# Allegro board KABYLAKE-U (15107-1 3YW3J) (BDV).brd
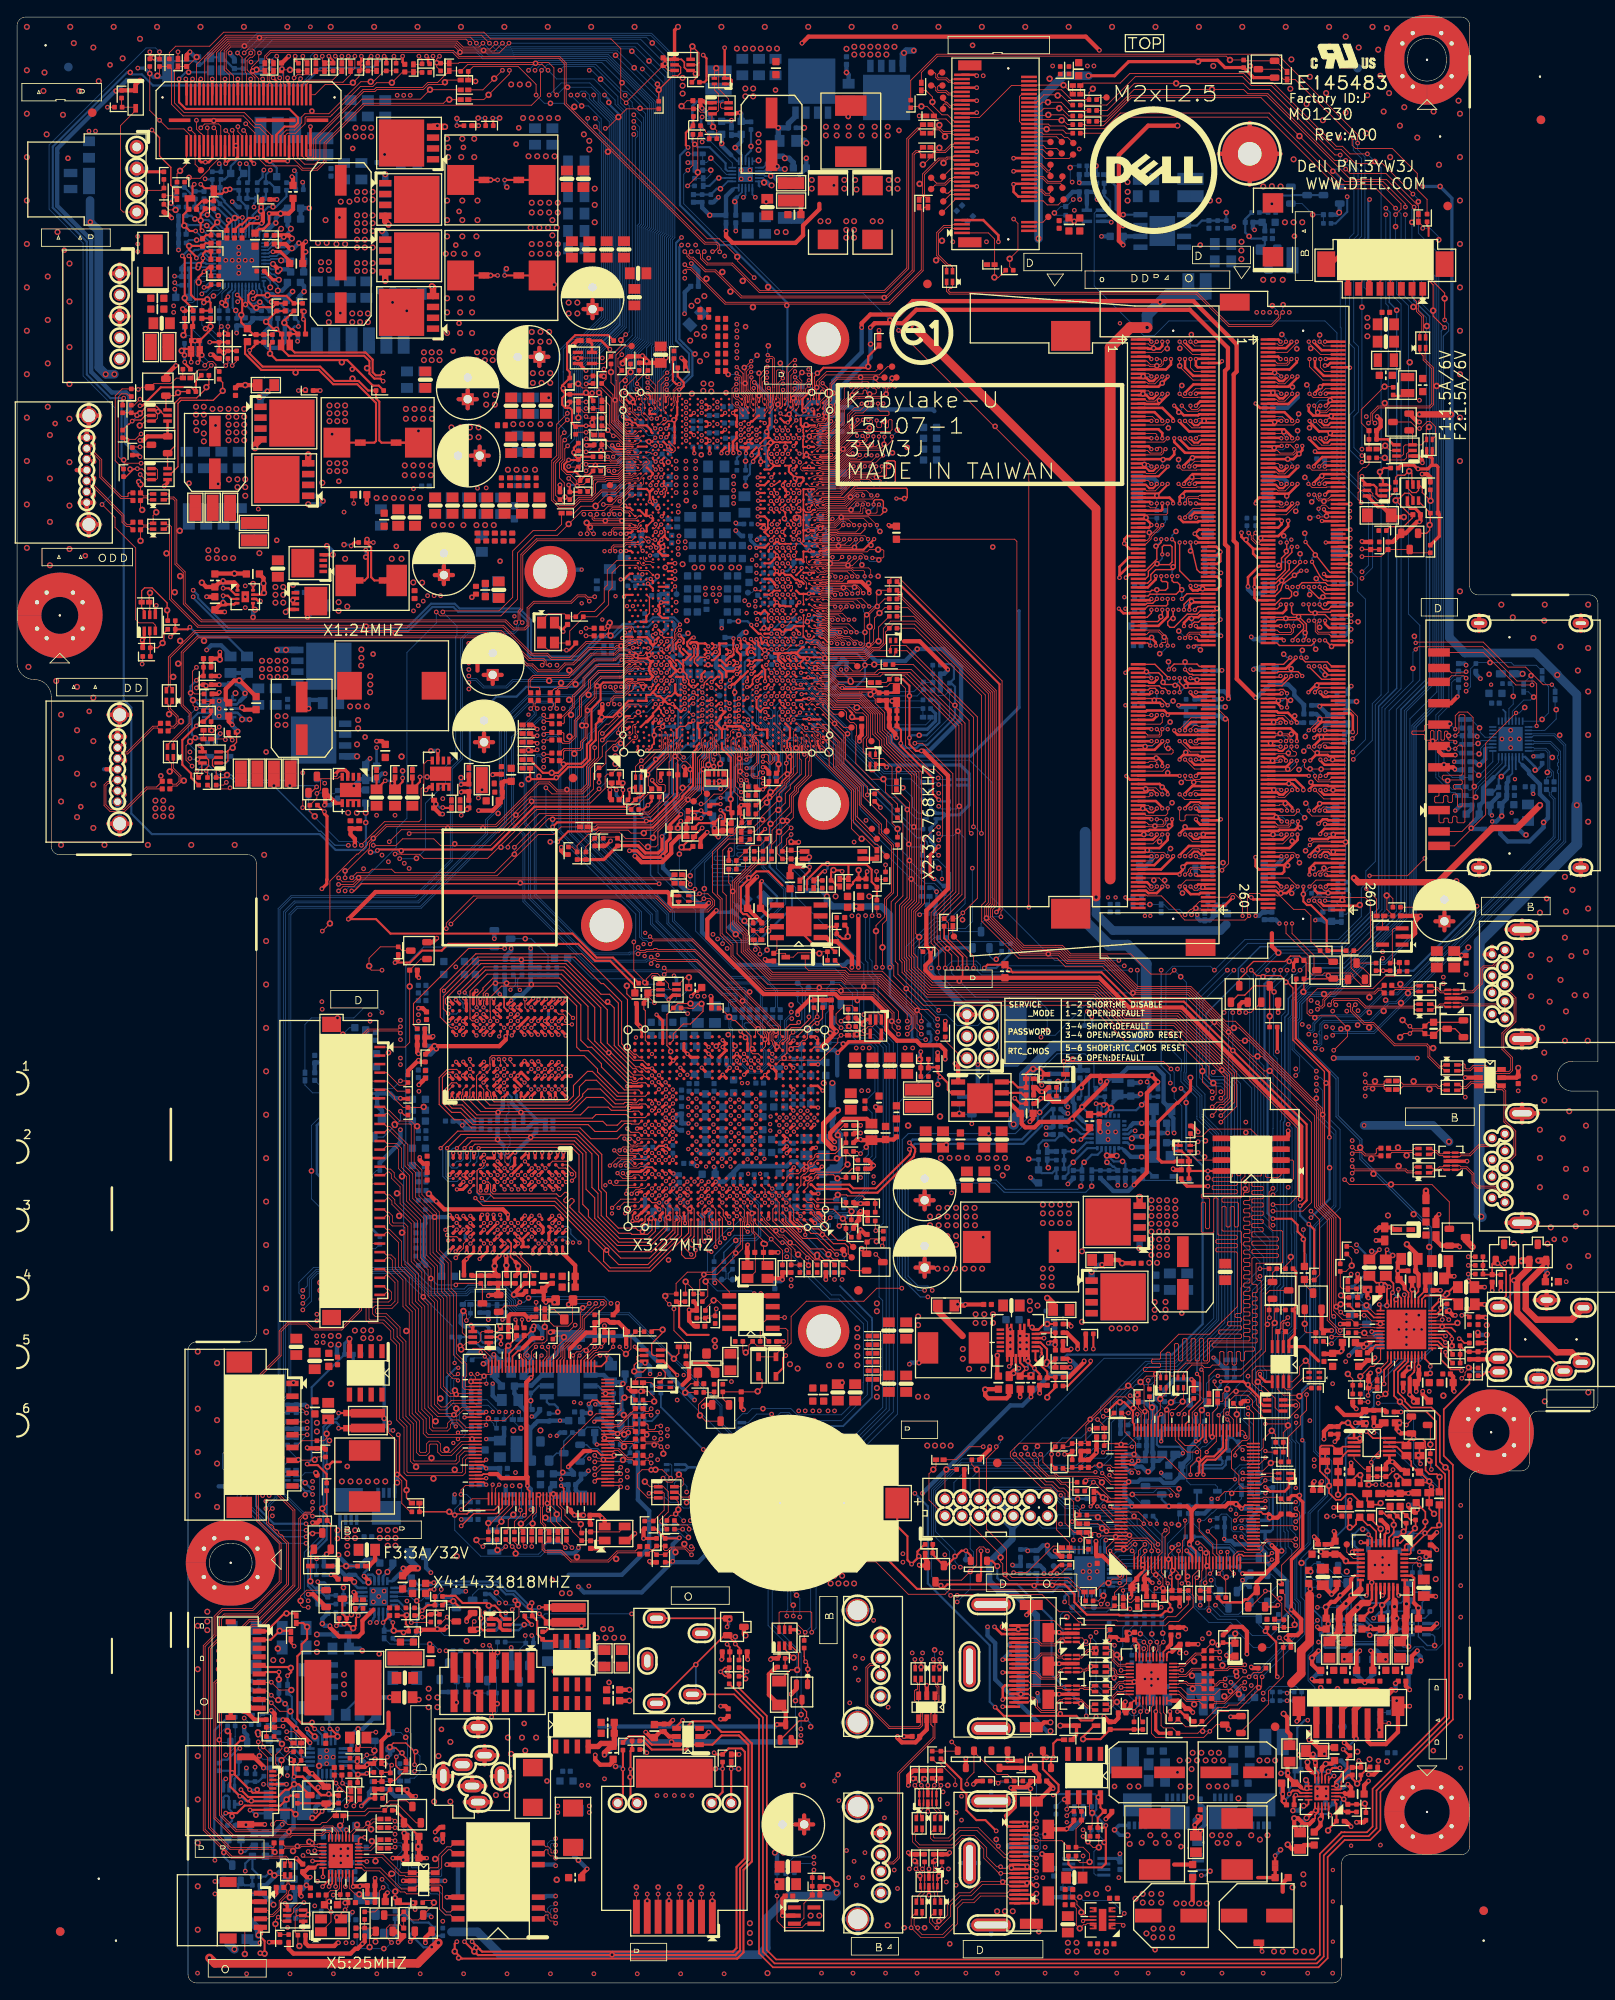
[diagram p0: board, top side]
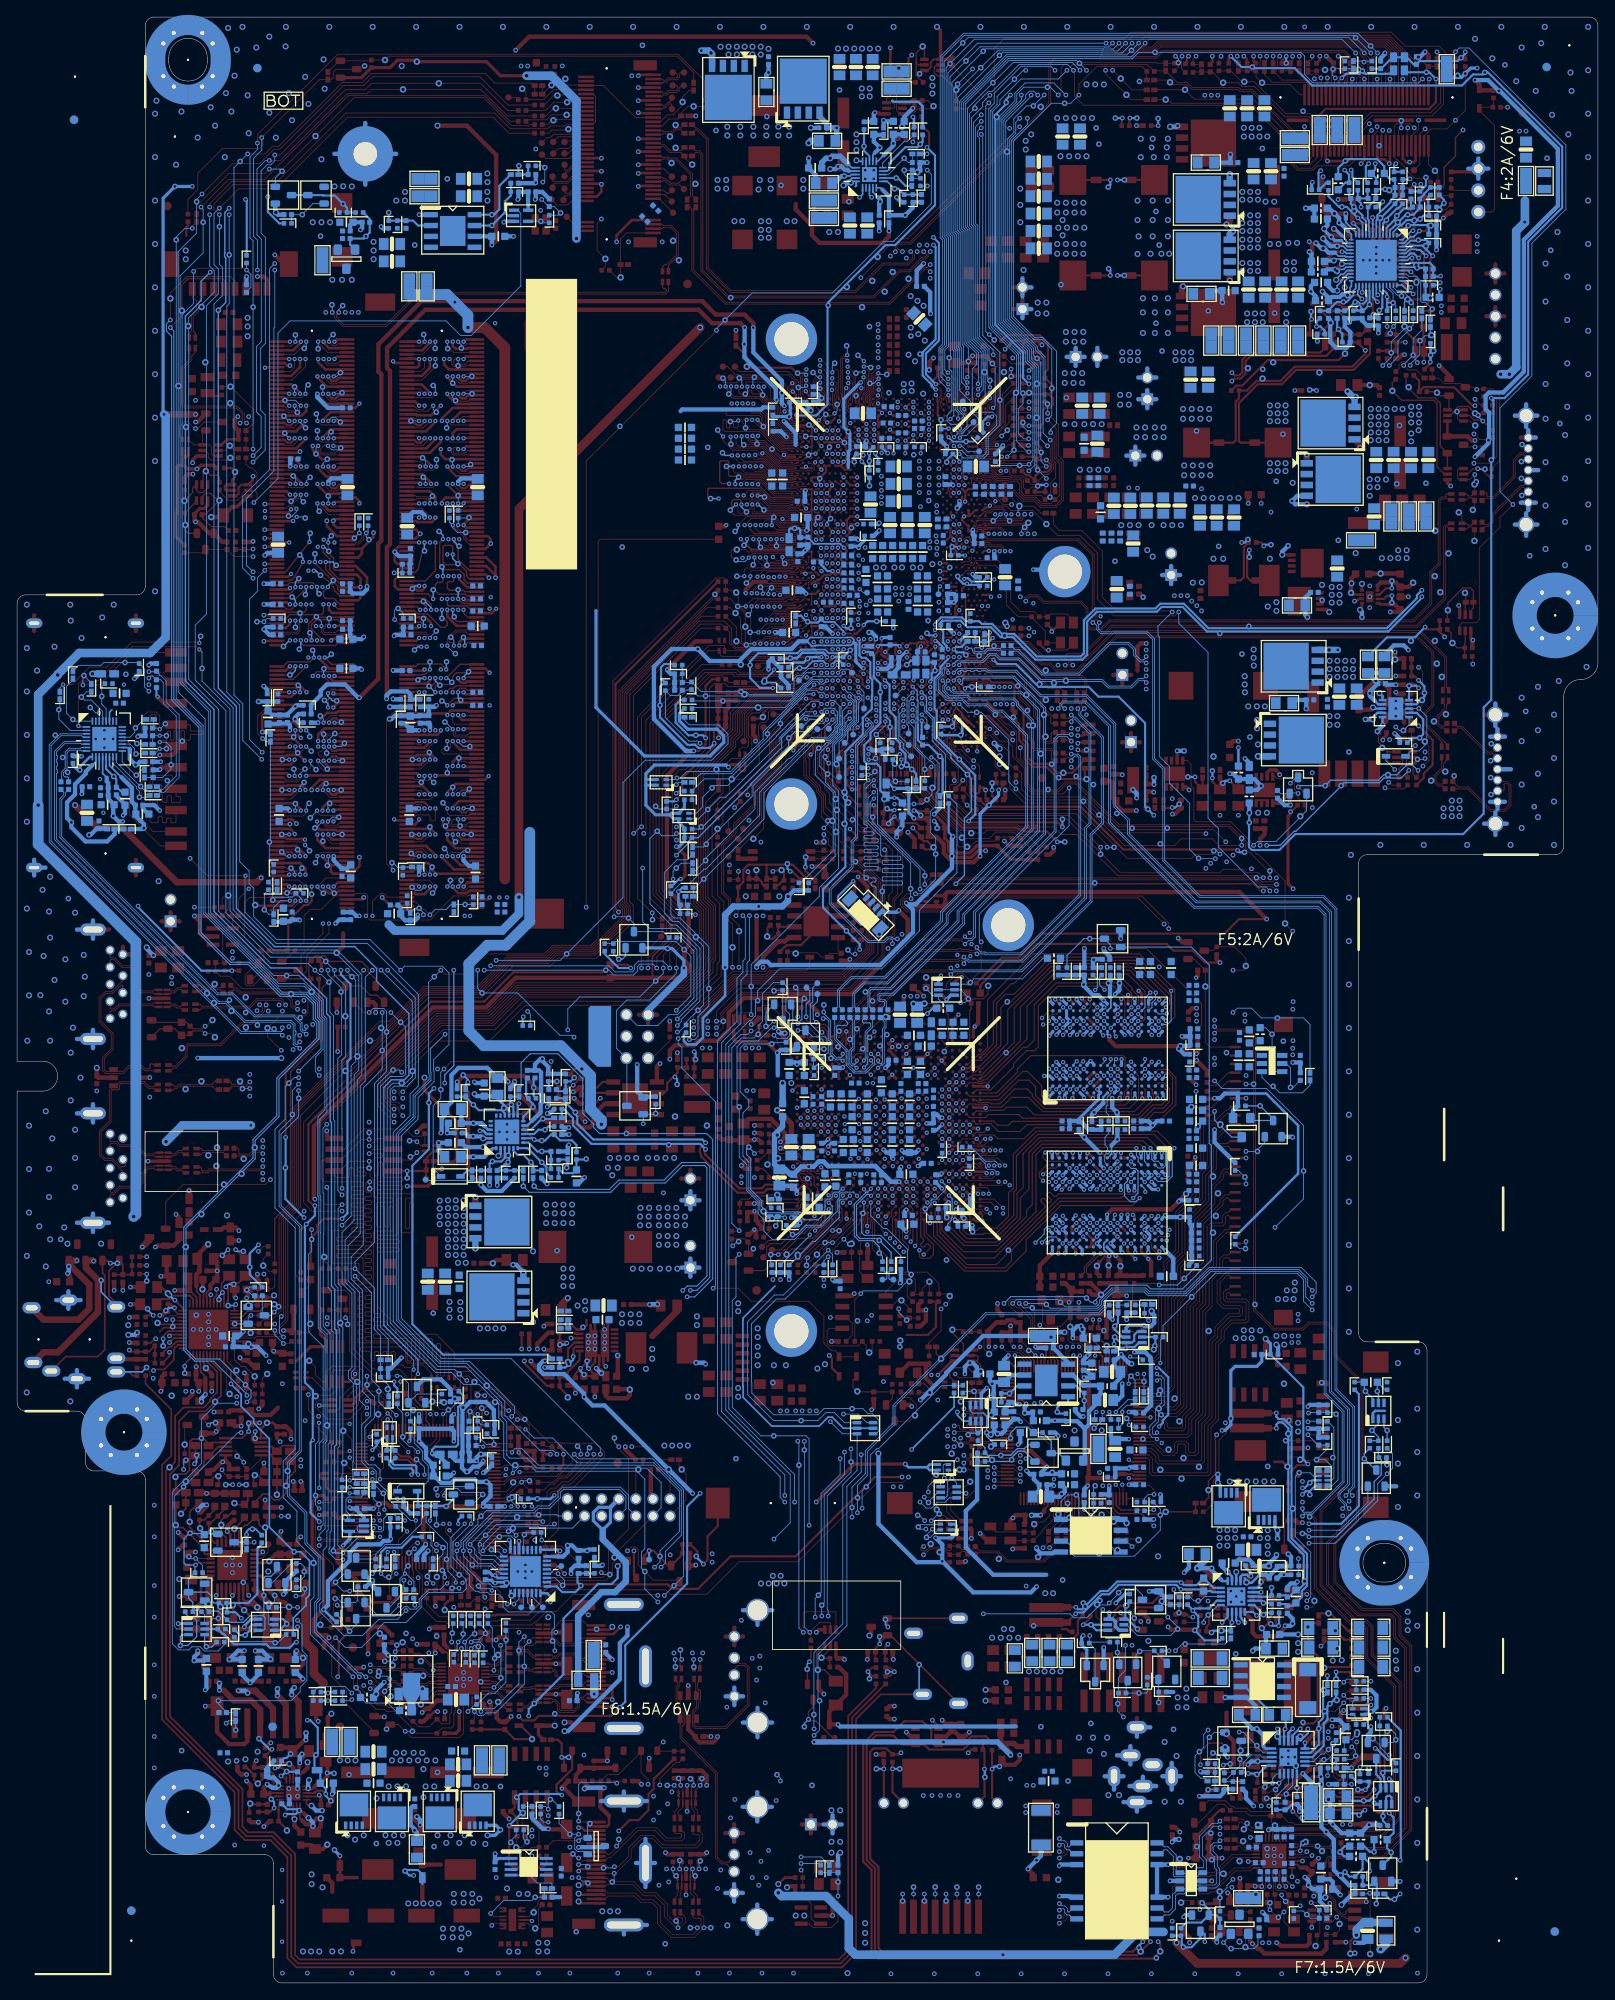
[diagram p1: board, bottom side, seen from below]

Outline 185 x 230 mm; copper layers: TOP, L2GND, L3, L4, L5GND, BOTTOM. Coordinates in mm from the lower left corner of the outline.
Outline path: 0,229 0,154.5 arc(0.59,153.09) 2,152.5 arc(3.41,151.91) 4,150.5 4,133 arc(4.29,132.29) 5,132 27,132 arc(27.71,131.71) 28,131 28,76 arc(27.71,75.29) 27,75 21,75 arc(20.29,74.71) 20,74 20,1 arc(20.29,0.29) 21,0 154,0 arc(154.71,0.29) 155,1 155,14 arc(155.29,14.71) 156,15 169,15 arc(169.71,15.29) 170,16 170,58.9 arc(170.29,59.61) 171,59.9 176,59.9 arc(176.71,60.19) 177,60.9 177,65.9 arc(177.29,66.61) 178,66.9 184,66.9 arc(184.71,67.19) 185,67.9 185,104.34 182,104.34 arc(180.25,106.09) 182,107.84 185,107.84 185,161.4 arc(184.71,162.11) 184,162.4 171,162.4 arc(170.29,162.69) 170,163.4 170,229 arc(169.71,229.71) 169,230 1,230 arc(0.29,229.71) 0,229 ; 24.75,51.4 25.25,51.4 arc(27.5,49.15) 25.25,46.9 24.75,46.9 arc(22.5,49.15) 24.75,51.4 ; 162.75,225.25 arc(165,227.5) 167.25,225.25 167.25,224.75 arc(165,222.5) 162.75,224.75 162.75,225.25

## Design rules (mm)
constraint set DEFAULT: min track width 0.127, pair gap 0.102
net group AUD_LINK_BCLK: nets AUD_LINK_BCLK HDA_BITCLK_CPU
net group CLK_WLAN_N: nets CLK_WLAN_N NGFF_REFCLKN0
net group CLK_WLAN_P: nets CLK_WLAN_P NGFF_REFCLKP0
net group DP_LANE0N_C: nets DP_LANE0N_C EDP_TX_CPU_N0
net group DP_LANE0P_C: nets DP_LANE0P_C EDP_TX_CPU_P0
net group DP_LANE1N_C: nets DP_LANE1N_C EDP_TX_CPU_N1
net group DP_LANE1P_C: nets DP_LANE1P_C EDP_TX_CPU_P1
net group GND: nets EC_AGND GND_AUD
net group GPU_ODT-MW: nets FBA_CMD2 FBA_CMD18
net group HDMI1_CK+: nets HDMI1_CK+ HDMI1_CK+_C
net group HDMI1_CK-: nets HDMI1_CK- HDMI1_CK-_C
net group HDMI1_D0+: nets HDMI1_D0+ HDMI1_D0+_C
net group HDMI1_D0-: nets HDMI1_D0- HDMI1_D0-_C
net group HDMI1_D1+: nets HDMI1_D1+ HDMI1_D1+_C
net group HDMI1_D1-: nets HDMI1_D1- HDMI1_D1-_C
net group HDMI1_D2+: nets HDMI1_D2+ HDMI1_D2+_C
net group HDMI1_D2-: nets HDMI1_D2- HDMI1_D2-_C
net group HDMI1_DATA_CPU_N0: nets HDMI1_DATA_CPU_N0 HDMI1_DATA_IC_N0
net group HDMI1_DATA_CPU_N1: nets HDMI1_DATA_CPU_N1 HDMI1_DATA_IC_N1
net group HDMI1_DATA_CPU_N2: nets HDMI1_DATA_CPU_N2 HDMI1_DATA_IC_N2
net group HDMI1_DATA_CPU_N3: nets HDMI1_DATA_CPU_N3 HDMI1_DATA_IC_N3
net group HDMI1_DATA_CPU_P0: nets HDMI1_DATA_CPU_P0 HDMI1_DATA_IC_P0
net group HDMI1_DATA_CPU_P1: nets HDMI1_DATA_CPU_P1 HDMI1_DATA_IC_P1
net group HDMI1_DATA_CPU_P2: nets HDMI1_DATA_CPU_P2 HDMI1_DATA_IC_P2
net group HDMI1_DATA_CPU_P3: nets HDMI1_DATA_CPU_P3 HDMI1_DATA_IC_P3
net group HDMI_LANE0_DN: nets HDMI_LANE0_DN HDMI_LANE0_IC_DN
net group HDMI_LANE0_DP: nets HDMI_LANE0_DP HDMI_LANE0_IC_DP
net group HDMI_LANE1_DN: nets HDMI_LANE1_DN HDMI_LANE1_IC_DN
net group HDMI_LANE1_DP: nets HDMI_LANE1_DP HDMI_LANE1_IC_DP
net group HDMI_LANE2_DN: nets HDMI_LANE2_DN HDMI_LANE2_IC_DN
net group HDMI_LANE2_DP: nets HDMI_LANE2_DP HDMI_LANE2_IC_DP
net group HDMI_LANE3_DN: nets HDMI_LANE3_DN HDMI_LANE3_IC_DN
net group HDMI_LANE3_DP: nets HDMI_LANE3_DP HDMI_LANE3_IC_DP
net group HSI_C_DN8: nets HSI_C_DN8 PCIE_RX_CPU_N8
net group HSI_C_DP8: nets HSI_C_DP8 PCIE_RX_CPU_P8
net group HSI_LAN_DN1_R: nets HSI_LAN_DN1_R PCIE_RX_CPU_N4
net group HSI_LAN_DP1_R: nets HSI_LAN_DP1_R PCIE_RX_CPU_P4
net group LAN_MDI2_DN: nets LAN_MDI2_DN LAN_MDI2_DN_R
net group LAN_MDI2_DP: nets LAN_MDI2_DP LAN_MDI2_DP_R
net group LAN_MDI3_DN: nets LAN_MDI3_DN LAN_MDI3_DN_R
net group LAN_MDI3_DP: nets LAN_MDI3_DP LAN_MDI3_DP_R
net group M1_SMB_CLK: nets M1_SMB_CLK SMB_CLK_RESUME
net group M1_SMB_DATA: nets M1_SMB_DATA SMB_DATA_RESUME
net group M_A_CLK0: nets M_A_CLK0 M_A_CLK#0
net group M_A_DQS0: nets M_A_DQS_DN0 M_A_DQS_DP0
net group M_A_DQS1: nets M_A_DQS_DN1 M_A_DQS_DP1
net group M_A_DQS2: nets M_A_DQS_DN2 M_A_DQS_DP2
net group M_A_DQS3: nets M_A_DQS_DN3 M_A_DQS_DP3
net group M_A_DQS4: nets M_A_DQS_DN4 M_A_DQS_DP4
net group M_A_DQS5: nets M_A_DQS_DN5 M_A_DQS_DP5
net group M_A_DQS6: nets M_A_DQS_DN6 M_A_DQS_DP6
net group M_A_DQS7: nets M_A_DQS_DN7 M_A_DQS_DP7
net group M_B_CLK0: nets M_B_CLK0 M_B_CLK#0
net group M_B_DQS0: nets M_B_DQS_DN0 M_B_DQS_DP0
net group M_B_DQS1: nets M_B_DQS_DN1 M_B_DQS_DP1
net group M_B_DQS2: nets M_B_DQS_DN2 M_B_DQS_DP2
net group M_B_DQS3: nets M_B_DQS_DN3 M_B_DQS_DP3
net group M_B_DQS4: nets M_B_DQS_DN4 M_B_DQS_DP4
net group M_B_DQS5: nets M_B_DQS_DN5 M_B_DQS_DP5
net group M_B_DQS6: nets M_B_DQS_DN6 M_B_DQS_DP6
net group M_B_DQS7: nets M_B_DQS_DN7 M_B_DQS_DP7
net group NGFF_PCIE0_RXN: nets NGFF_PCIE0_RXN PCIE_RX_CPU_N5
net group NGFF_PCIE0_RXP: nets NGFF_PCIE0_RXP PCIE_RX_CPU_P5
net group PCIE_TX_CON_N4: nets PCIE_TX_CON_N4 PCIE_TX_CPU_N4
net group PCIE_TX_CON_N8: nets PCIE_TX_CON_N8 PCIE_TX_CPU_N8
net group PCIE_TX_CON_P4: nets PCIE_TX_CON_P4 PCIE_TX_CPU_P4
net group PCIE_TX_CON_P8: nets PCIE_TX_CON_P8 PCIE_TX_CPU_P8
net group PEG_C_TXN0: nets PEG_C_TXN0 PEG_TXN0
net group PEG_C_TXN1: nets PEG_C_TXN1 PEG_TXN1
net group PEG_C_TXN2: nets PEG_C_TXN2 PEG_TXN2
net group PEG_C_TXN3: nets PEG_C_TXN3 PEG_TXN3
net group PEG_C_TXP0: nets PEG_C_TXP0 PEG_TXP0
net group PEG_C_TXP1: nets PEG_C_TXP1 PEG_TXP1
net group PEG_C_TXP2: nets PEG_C_TXP2 PEG_TXP2
net group PEG_C_TXP3: nets PEG_C_TXP3 PEG_TXP3
net group PEG_CLK_CPU: nets PEG_CLK_CPU PEG_CLK_XDP
net group PEG_CLK_CPU#: nets PEG_CLK_CPU# PEG_CLK_XDP#
net group POWER_CPU_PLL_20_5: nets 1V_VCCPRIM 1V_VCCSRAM
net group RCOMP_PCIE: nets PEG_RCOMPN_CPU PEG_RCOMPP_CPU
net group SD_CLK_C_1: nets SD_CLK_C_1 SP3
net group SD_CMD: nets SD_CMD SP4
net group SD_DAT0: nets SD_DAT0 SP2
net group SD_DAT1: nets SD_DAT1 SP1
net group SD_DAT2: nets SD_DAT2 SP6
net group SD_DAT3: nets SD_DAT3 SP5
net group SIDE_USB3_RX0+: nets SIDE_USB3_RX0+ USB30_RX_CPU_P0
net group SIDE_USB3_RX0-: nets SIDE_USB3_RX0- USB30_RX_CPU_N0
net group SIDE_USB3_RX1+: nets SIDE_USB3_RX1+ USB30_RX_CPU_P1
net group SIDE_USB3_RX1-: nets SIDE_USB3_RX1- USB30_RX_CPU_N1
net group SMB_CLK_MAIN: nets SMB_CLK_MAIN XDP_SMBCLK
net group SMB_DATA_MAIN: nets SMB_DATA_MAIN XDP_SMBDAT
net group SPI_CLK: nets SPI_CLK SPI_CLK_CPU
net group SPI_CS0_N: nets SPI_CS0_N SPI_CS_CPU_N0
net group SPI_MOSI: nets SPI_MOSI SPI_SI_CPU
net group STRAP: nets GPP_B18/GSPI0_MOSI GPP_B22/GSPI1_MOSI
net group TRANSFORNER_20_10: nets MCT_R_1 XRF_TDC2
net group USB2_N0: nets USB2_N0 USBP0N_EXT
net group USB2_N3: nets USB2_N3 USB3N_EXT
net group USB2_N4: nets USB2_N4 USB_PCH_DN4_NN
net group USB2_N5: nets USB2_N5 USB_TOUCH_N
net group USB2_N6: nets USB2_N6 USB2_NGFF_N6
net group USB2_NGFF_P6: nets USB2_NGFF_P6 USB2_P6
net group USB2_P0: nets USB2_P0 USBP0P_EXT
net group USB2_P3: nets USB2_P3 USB3P_EXT
net group USB2_P4: nets USB2_P4 USB_PCH_DP4_PP
net group USB2_P5: nets USB2_P5 USB_TOUCH_P
net group USB2N_EXT: nets USB2_N2 USB2N_EXT
net group USB2P_EXT: nets USB2_P2 USB2P_EXT
net group USB_CPU_P1-DIFF143: nets USB2_N1 USB2_P1
net group AUD_LINK_SDO: nets AUD_LINK_SDO AUD_LINK_SDO_N HDA_SDOUT_CPU
net group AUDIO_AMP-MW: nets TPA3131_FAULT#
net group AUDIO_AMP_15: nets AMP_SPKR_L AMP_SPKR_R AMP_SWITCH_C_L AMP_SWITCH_C_R PORTC_SPK_L PORTC_SPK_L_1 PORTC_SPK_R PORTC_SPK_R_1 SCALAR_OUT_L SCALAR_OUT_L_C SCALAR_OUT_R SCALAR_OUT_R_C SPEAKER1_L1 SPEAKER1_R1 SPKR_IN_L SPKR_IN_R TP3131_GVDD TPA3131_GAIN TPA3131_LINN TPA3131_LINN_1 TPA3131_MUTE TPA3131_PLIMIT TPA3131_RINN TPA3131_RINN_1
net group AUDIO_DMIC_MW: nets AUD_DMIC_CLK AUD_DMIC_CLK_R AUD_DMIC_CLK_R_1 AUD_DMIC_DATA AUD_DMIC_DATA_R
net group AUDIO_HDA: nets AUD_BEEP_C AUD_BEEP_R AUD_LINK_RST_N AUD_LINK_RST_N_R AUD_LINK_SDIN AUD_LINK_SDIN_1 AUD_LINK_SDO_1 AUD_LINK_SDO_R1 AUD_LINK_SYNC BUZZER_SPKR_R HDA_RST#_CPU HDA_SYNC_CPU PCH_AUD_RST_N PCH_AUD_RST_N_1 SENSE_A SENSE_A_C SENSE_B SLEEVE_G SPDIF_IC
net group AUDIO_IO: nets AUD_GP3 EAPD_DEPOP HPOL_CON HPOR_CON HPOUT-JD HPOUT-L HPOUT-R LINE2-VREFO LINEOUT-JD LINEOUT-L LINEOUT-R LINEOUT_C-L LINEOUT_C-R LINEOUT_CON-L LINEOUT_CON-R MIC2-L MIC2-L-1 MIC2-R MIC2-R-1 MIC2-VREFO-L MIC2-VREFO-R
net group AUDIO_IO_REF: nets JDREF MIC-CAP VRP
net group AUDIO_SPK_CN: nets SPKR_L+_SNB SPKR_L-_SNB SPKR_OUT_L+ SPKR_OUT_L- SPKR_OUT_R+ SPKR_OUT_R- SPKR_R+_SNB SPKR_R-_SNB TPA3131_BSNL TPA3131_BSNR TPA3131_BSPL TPA3131_BSPR
net group CARD_READER-MWS: nets SD_CD# SD_WP SP7
net group CFG-MW: nets BPM_CPU_N2 BPM_CPU_N3 CFG0 CFG1 CFG2 CFG3 CFG4 CFG5 CFG6 CFG7 CFG8 CFG9 CFG10 CFG11 CFG12 CFG13 CFG14 CFG15 CFG16 CFG17 CFG18 CFG19
net group CHARGER_4_5-MW: nets AC_IN AC_OK# AC_PRESENT AC_PROTECT AD_IA AD_IA_HW1 AD_IA_HW2 AD_IA_R BAT_ALERT BAT_IN# BAT_IN#_1 CHG_ON# SYS_PRES
net group CLK_REQ_N: nets CR_CLKREQ_R CRCLK_REQ_N LANCLK_REQ_N LANCLK_REQ_U_N NGFFCLK_REQ_N PEG_CLKREQ0_CPU# PEG_CLKREQ4_CPU# PEG_CLKREQ5_CPU#
net group CLOCK-MW: nets LPC_CLK0 LPC_CLK0_R LPC_CLK1 LPC_CLK1_R LPC_CLK_D SUS_CLK SUS_CLK_EC SUS_CLK_PCH
net group CONVERTER_4_5-MW: nets LEDC_ISET LPF RT SSTCMP SSTCMP_1 STATUS VREF
net group CONVERTER_10_10: nets ISEN1 ISEN2 ISEN3 ISEN4 ISW OZ554_PWM RTN1 RTN2 RTN3 RTN4
net group CONVERTER_20_10: nets LDR LDR_1 OZ554_VIN SNB
net group DP_AUXN_C: nets DP_AUXN_C EDP_AUX_CPU_N RTD_PIN113
net group DP_AUXP_C: nets DP_AUXP_C EDP_AUX_CPU_P RTD_PIN112
net group DP_HPD-MW: nets 2136_HPD_C DDSP_B_HPD_CONN DP_HPD EDP_HPD_CPU HDMI1_OUT_HPD HDMI_HDCP_READY HDMI_HPDET
net group DPU_GPIO: nets GPIO1_FBVDDQCTL GPIO2_BL_PWM GPIO3_PPEN_R GPIO4_BLEN GPIO5_PWM_VID_BOOT_EN GPIO7_3D_STEREO GPIO8_OVERT# GPIO9_ALERT# GPIO10_MEM_VREF_CTL GPIO11_PWM_VID GPIO12_AC_DETECT GPIO13_NVVDD_PSI
net group FAN_PWM: nets BKLT_ADJ CPU_FAN_CTRL_SIO CPU_FAN_TACH_SIO DPLVDS_PWMIN DPLVDS_PWMOUT L_BKLTCTL LVDS_BL_ADJ
net group GPIO_4-MW: nets ADAPTOR_PSID ADAPTOR_PSID_R ALERT# BIST_DISABLE BIST_EN_INV BIST_ENABLE BIST_ENABLE_1 BIST_PIN25 DB_UART1_RX DB_UART1_TX DDC_WP DDC_WP_1 DDR_VTT_CNTL_L1 DDR_VTT_CNTL_L2 DDR_VTT_CNTL_L3 DET_HDMI# DET_HDMI_C DISP_UTIL_CPU DPLVDS_HPD EAPD_DEPOP_1 EAPD_DEPOP_2_D EC_BEEP_GPIO EC_BEEP_GPIO_R EC_CLEAR_RTC EC_OSD_MENU EC_SCI# EC_SCI#_R EC_SERIRQ EC_SMI# EC_SMI#_R EC_SPKR EC_SWI# EC_SWI#_R ECRST# EDID_RDY ESPI_RST# EXT_PWR_GATE# FIVR_EN_R FLASH_WP GPD2/LAN_WAKE# GPIO GPIO0_TPM GPIO1_TPM GPIO2_TPM GPP_B23/SML1ALERT# GPP_C2/SMBALERT# GPP_C5/SML0ALERT# H_RCIN# H_RCIN#_R HDMI_DET_SIO HDMI_IN_DET#_R HP_MUTE IMS_SCALAR ITP_PMODE JACK_PSID KBC_ON#_GATE KBC_ON#_GATE_L LAN_DISABLE_N LVDS_DET_A* LVDS_DET_B* M_A_EVENT# M_B_EVENT# MINI_POWER_CTRL MODEL_ID_DET MONITOR_NAME_ID0 MONITOR_NAME_ID1 MPCIE_DISABLE_N NGFF_ALERT# NGFF_BT_DISABLE NGFF_BT_DISABLE_EC NGFF_DETECT_PCIE NGFF_DETECT_PCIE_C NGFF_DETECT_USB NGFF_DETECT_USB_C OS_MODE_SEL OSD_BIST_N OSD_CONTROL_SEL OSD_DN OSD_DN_CPU OSD_DN_R OSD_MENU OSD_MENU_CPU OSD_MENU_R OSD_UP OSD_UP_CPU OSD_UP_R PANEL_SEL1_CABLE_C PANEL_SEL1_CABLE_S PANEL_SEL2_CABLE_C PANEL_SEL2_CABLE_S PANEL_SEL3_CABLE_C PANEL_SEL3_CABLE_S PC_MONITOR_SW PCB_VER_ID PCH_DPWROK_EC13 PCH_DPWROK_EC76 PCIE_CLKREQ1_CPU_N PCIE_CLKREQ2_CPU_N PCIE_CLKREQ3_CPU_N PIRQA# PM_CLKRUN#_EC PROC_SELECT# PSID_D PSID_D_1 PSID_G PSL_IN1# PSL_IN2# PSL_OUT# PURE_HW_SHUTDOWN# PW_CLEAR PWR_CHG_AD_OFF PWRCN_DET_N RTC_DET# S5_ENABLE SA0_DIMM1 SA0_DIMM2 SA1_DIMM1 SA1_DIMM2 SA2_DIMM1 SA2_DIMM2 SCALAR_MUTE SD_WAKE#_IC SERIRQ_CPU SERIRQ_TPM SIO_EUP_EN SIO_GPU_EN SIO_HDD_LED SIO_HDD_LED_1 SKEW1 SKEW2 SKEW3 SKTOCC# SLP_WLAN_N SMBUS_ISP SPKR_DET SPKR_DET_C T_CRIT# THERM_SYS_SHDN# TP_DET_N USB2_ID USB2_PWR_EN USB3_PWR_EN USB_EN_S3WAKE USB_OC#0_1 USB_OC#2_3 VD1_EN# VD_IN1 VD_IN2 VD_OUT1# VD_OUT2# VSS_AY3 WEBCAM_DET_N
net group GPIO_PWR_CTRL: nets AD_OFF_L ADP_V_DET HDA_SPKR HP_MUTE_D HP_MUTE_L LVDS_PU_6_1 ME_CNTL1 N37189306 PANEL_ON1 PANEL_ON2 PANEL_ON3 PC_MONITOR_SW_G PCH_PWROK_C_1 PCH_PWROK_C_2 PCH_PWROK_C_3 PD4405_A PD4405_K PQ4206_D PQ4406_2 PQ4406_3 PQ4406_5 PQ4406_6 PQ4409_C PQ4409_E PWR_CHG_AD_OFF_R PWR_VDDQ_PG_N PWRGD_3V_B PWRGD_3V_C Q9664_D RSMRST_N_B SCALAR_PC_SW1 SCALAR_PC_SW2 SCALAR_PC_SW3 SCALAR_PC_SW4 SCALAR_PC_SW5 SLP_SUSB_C SLP_SUSB_R TPA3113_SD TPA3113_SD1# VCCIO_EN_C_1 VCCIO_EN_C_2 VCCIO_EN_C_3 VCCIO_EN_C_4 VCCST_GD_1 VCCST_GD_2 VCCSTU_EN_C_1 VCCSTU_EN_C_2 VCCSTU_EN_C_3 VCCSTU_EN_C_4 VR_EN_C_1 VR_EN_C_2
net group GPU_ADDRESS-MW: nets FBA_CMD4 FBA_CMD5 FBA_CMD6 FBA_CMD7 FBA_CMD8 FBA_CMD9 FBA_CMD10 FBA_CMD11 FBA_CMD20 FBA_CMD21 FBA_CMD22 FBA_CMD23 FBA_CMD24 FBA_CMD25 FBA_CMD28 FBA_CMD29
net group GPU_CTRL-MW: nets FBA_CMD0 FBA_CMD1 FBA_CMD3 FBA_CMD12 FBA_CMD13 FBA_CMD14 FBA_CMD15 FBA_CMD16 FBA_CMD17 FBA_CMD19 FBA_CMD26 FBA_CMD27 FBA_CMD30 FBA_CMD31
net group GPU_DATA-MW: nets MDA0 MDA1 MDA2 MDA3 MDA4 MDA5 MDA6 MDA7 MDA8 MDA9 MDA10 MDA11 MDA12 MDA13 MDA14 MDA15 MDA16 MDA17 MDA18 MDA19 MDA20 MDA21 MDA22 MDA23 MDA24 MDA25 MDA26 MDA27 MDA28 MDA29 MDA30 MDA31 MDA32 MDA33 MDA34 MDA35 MDA36 MDA37 MDA38 MDA39 MDA40 MDA41 MDA42 MDA43 MDA44 MDA45 MDA46 MDA47 MDA48 MDA49 MDA50 MDA51 MDA52 MDA53 MDA54 MDA55 MDA56 MDA57 MDA58 MDA59 MDA60 MDA61 MDA62 MDA63
net group GPU_DBI: nets FBA_DBI0 FBA_DBI1 FBA_DBI2 FBA_DBI3 FBA_DBI4 FBA_DBI5 FBA_DBI6 FBA_DBI7
net group GPU_EDC: nets FBA_EDC0 FBA_EDC1 FBA_EDC2 FBA_EDC3 FBA_EDC4 FBA_EDC5 FBA_EDC6 FBA_EDC7
net group GPU_OTHER_4-6-MW: nets BUFRST_N FB_VREF FBA_DEBUG0 FBA_DEBUG1 FBA_VREF_FET_H FBA_VREF_FET_L GC6_FB_EN GPIO6_FB_CLAMP_TGL_REQ GPIO_FB_CLAMP_GPU GPU_TESTMODE GPU_THERM_SHUTDOWN_N GPU_VCC3_CTL GPU_VCC3_CTL_2 IFPA_IOVDD IFPAB_PLLVDD_1 IFPAB_PLLVDD_2 IFPB_IOVDD IFPC_IOVDD IFPC_PLLVDD_1 IFPC_PLLVDD_2 IFPD_IOVDD IFPD_PLLVDD_1 IFPD_PLLVDD_2 IFPE_IOVDD IFPEF_PLLVDD_1 IFPEF_PLLVDD_2 IFPF_IOVDD JTAG_TCLK JTAG_TDI JTAG_TDO JTAG_TMS JTAG_TRST PEX_TERMP PEX_TSTCLK_OUT PEX_TSTCLK_OUT# STRAP0 STRAP1 STRAP2 STRAP3 STRAP4 STRAP_REF0
net group GPU_VREF: nets DACA_VREF FBA_SEN0 FBA_SEN2 FBA_SOE0 FBA_SOE1 FBA_SOE2 FBA_SOE3 FBA_VREFC0 FBA_VREFC1 FBA_VREFD_H FBA_VREFD_L FBA_ZQ0 FBA_ZQ1 FBA_ZQ2 FBA_ZQ3
net group HDMI-MW: nets CFG DCIN_EN DDCBUF EQ ISET PD_N PRE REXT
net group LAN_OTHER_4-5-MW: nets LAN_RSET RTL_ISOLATE_N RTL_ISOLATE_N_1 RTL_ISOLATE_N_2
net group LED_10_6: nets BATT_AMBER_LED#_C BATT_WHITE_LED#_C LAN_LEDACT_R# LINK_ACTIVITY_N LINK_PWR PB_IN_SW1 PCH_SATA_LED_1 PCH_SATA_LED_R PWR_LED_YELLOW_C PWR_LED_YELLOW_C2 Q1212_G SATA_LED_N SIO_GREEN_PWM SIO_YELLOW SPEED_100*_CON SPEED_100_N SPEED_1000*_CON SPEED_1000_N SUS_LED_GREEN_C SUS_LED_GREEN_C2
net group LPC-MW: nets FWH_ID0 INIT_3V L_AD0 L_AD1 L_AD2 L_AD3 L_FRAME_N L_FRAME_N_R LPC_CLKRUN#_CPU LPC_PME# LPC_PME_N PM_CLKRUN#_TPM
net group M_A_CLK1: nets M_A_CLK#1
net group M_A_CLK TO DQS: nets M_A_CLK1
net group M_A_COMMAND: nets M_A_A0 M_A_A1 M_A_A2 M_A_A3 M_A_A4 M_A_A5 M_A_A6 M_A_A7 M_A_A8 M_A_A9 M_A_A10 M_A_A11 M_A_A12 M_A_A13 M_A_A14 M_A_A15 M_A_BS0 M_A_BS1
net group M_A_CTRL: nets M_A_CKE0 M_A_CKE1 M_A_CS#0 M_A_CS#1 M_A_ODT0 M_A_ODT1
net group M_A_DATA0: nets M_A_DQ0 M_A_DQ1 M_A_DQ2 M_A_DQ3 M_A_DQ4 M_A_DQ5 M_A_DQ6 M_A_DQ7
net group M_A_DATA1: nets M_A_DQ8 M_A_DQ9 M_A_DQ10 M_A_DQ11 M_A_DQ12 M_A_DQ13 M_A_DQ14 M_A_DQ15
net group M_A_DATA2: nets M_A_DQ16 M_A_DQ17 M_A_DQ18 M_A_DQ19 M_A_DQ20 M_A_DQ21 M_A_DQ22 M_A_DQ23
net group M_A_DATA3: nets M_A_DQ24 M_A_DQ25 M_A_DQ26 M_A_DQ27 M_A_DQ28 M_A_DQ29 M_A_DQ30 M_A_DQ31
net group M_A_DATA4: nets M_A_DQ32 M_A_DQ33 M_A_DQ34 M_A_DQ35 M_A_DQ36 M_A_DQ37 M_A_DQ38 M_A_DQ39
net group M_A_DATA5: nets M_A_DQ40 M_A_DQ41 M_A_DQ42 M_A_DQ43 M_A_DQ44 M_A_DQ45 M_A_DQ46 M_A_DQ47
net group M_A_DATA6: nets M_A_DQ48 M_A_DQ49 M_A_DQ50 M_A_DQ51 M_A_DQ52 M_A_DQ53 M_A_DQ54 M_A_DQ55
net group M_A_DATA7: nets M_A_DQ56 M_A_DQ57 M_A_DQ58 M_A_DQ59 M_A_DQ60 M_A_DQ61 M_A_DQ62 M_A_DQ63
net group M_B_CLK1: nets M_B_CLK#1
net group M_B_CLK TO DQS: nets M_B_CLK1
net group M_B_COMMAND: nets M_B_A0 M_B_A1 M_B_A2 M_B_A3 M_B_A4 M_B_A5 M_B_A6 M_B_A7 M_B_A8 M_B_A9 M_B_A10 M_B_A11 M_B_A12 M_B_A13 M_B_A14 M_B_A15 M_B_BS0 M_B_BS1
net group M_B_CONTROL: nets M_B_CKE0 M_B_CKE1 M_B_CS#0 M_B_CS#1 M_B_ODT0 M_B_ODT1
net group M_B_DATA0: nets M_B_DQ0 M_B_DQ1 M_B_DQ2 M_B_DQ3 M_B_DQ4 M_B_DQ5 M_B_DQ6 M_B_DQ7
net group M_B_DATA1: nets M_B_DQ8 M_B_DQ9 M_B_DQ10 M_B_DQ11 M_B_DQ12 M_B_DQ13 M_B_DQ14 M_B_DQ15
net group M_B_DATA2: nets M_B_DQ16 M_B_DQ17 M_B_DQ18 M_B_DQ19 M_B_DQ20 M_B_DQ21 M_B_DQ22 M_B_DQ23
net group M_B_DATA3: nets M_B_DQ24 M_B_DQ25 M_B_DQ26 M_B_DQ27 M_B_DQ28 M_B_DQ29 M_B_DQ30 M_B_DQ31
net group M_B_DATA4: nets M_B_DQ32 M_B_DQ33 M_B_DQ34 M_B_DQ35 M_B_DQ36 M_B_DQ37 M_B_DQ38 M_B_DQ39
net group M_B_DATA5: nets M_B_DQ40 M_B_DQ41 M_B_DQ42 M_B_DQ43 M_B_DQ44 M_B_DQ45 M_B_DQ46 M_B_DQ47
net group M_B_DATA6: nets M_B_DQ48 M_B_DQ49 M_B_DQ50 M_B_DQ51 M_B_DQ52 M_B_DQ53 M_B_DQ54 M_B_DQ55
net group M_B_DATA7: nets M_B_DQ56 M_B_DQ57 M_B_DQ58 M_B_DQ59 M_B_DQ60 M_B_DQ61 M_B_DQ62 M_B_DQ63
net group MEM_A_CMD-MW: nets DDR0_A_ALERT_N DDR0_A_PARITY M_A_ACT_N M_A_BG0 M_A_BG1
net group MEM_A_CTRL_CKE-MW: nets M_A_A16
net group MEM_B_CMD-MW: nets DDR1_B_ALERT_N DDR1_B_PARITY M_B_ACT_N M_B_BG0 M_B_BG1
net group MEM_B_CTRL_CKE-MW: nets M_B_A16
net group MEM_VREF: nets DDR_VREF_CA DIMM_CA_CPU_VREF_A_RC DIMM_CA_VREF_A_R DIMM_CB_CPU_VREF_A_RC DIMM_CB_VREF_A_R M_VREF_DQ_DIM0 M_VREF_DQ_DIM0_R M_VREF_DQ_DIM0_RC M_VREF_DQ_DIM1
net group NGFF_CLCCK-MW: nets NGFF_CLKREQ0_N NGFF_CLKREQ1_N SUSCLK_NGFF
net group NGFF_OTHER-MW: nets NGFF_ALERT_N NGFF_CLKREQ0_NGFF# NGFF_CLKREQ1_N_TP NGFF_PEWAKE0_N NGFF_POWER_CTRL_1 NGFF_W_DISABLE1_N NGFF_W_DISABLE2_N
net group NGFF_PCIE0_TXN: nets NGFF_PCIE0_TXN PCIE_TX_CON_N5 PCIE_TX_CPU_N5
net group NGFF_PCIE0_TXP: nets NGFF_PCIE0_TXP PCIE_TX_CON_P5 PCIE_TX_CPU_P5
net group OSCILLATION-MW: nets 14MHZ_IN_SCALAR 14MHZ_OUT_SCALAR LAN_XTALI LAN_XTALO LAN_XTALO_C XTAL_OUTBUFF XTAL_SSFOUT XTALIN XTALOUT
net group OTHER_4_5-MW: nets 1117_ADJ PB_IN_N_1 SYS_FAN_TACH1_1 SYS_FAN_TACH1_2 SYSTEM_FAN_PWM1_1
net group PANEL_CONTROL-MW: nets BKLT_EN BKLT_EN1 DPLVDS_BL_EN DPLVDS_PANEL_VCC LVDS_DET_B_C* LVDS_PU_5 LVDS_PU_6 LVDS_PU_24 PANEL_ON_1 PANEL_ON_2 PANEL_ON_3 PANEL_SEL1_CABLE PANEL_SEL2_CABLE PANEL_SEL3_CABLE S_LVDS_BL_EN
net group PCIE_CLK_REQ: nets PEX_CLKREQ
net group PECI: nets EC_PECI EC_PECI_R PECI_EC
net group PECI_THERMTRIP-MW: nets EC_PROCHOT# EC_PROCHOT#_G H_PROCHOT_N PCH_THERMTRIP_N PROCHOT#_CPU THERMTRIP#_CPU
net group POWER_10_10: nets 1V1_EN 3P3V_SPI DDC5V_HDMI DDC5V_HDMI_R EC_VBKUP EC_VTT HDMI_OUT_DDC_VCC PWR_3D3V_FB2_A PWR_5V_CS1 PWR_5V_EN1 PWR_5V_FB1_A PWR_5V_LDO5 SD_VDD2 V_5P0_A VCCRTCEXT VDDQ_BLEED_R2 VSS_AY71
net group POWER_12_10_REF: nets RREF
net group POWER_15_20: nets PWR_5V_BYP1
net group POWER_20_5: nets 3D3V_AUX_KBC 3D3V_AUX_KBC_VCC +19V_AMP_AVCC ADC_3V3 AUDIO_3V3 AV12 AV12_L DV12S DV33_18 EC_AVCC HDMI_5V MHL_3V3 RTD2506S_VREF RX_3V3 SDREG2 V_3_CARD VCCK_1V1 VDDQ_BLEED_R1
net group POWER_40_5: nets DCBATOUT_RT6575_1
net group POWER_50_5: nets 1V_EOPIO 1V_VCCPRIM_CORE 3V3AUX PWR_1D0V_VCC PWR_VDDQ_VDDQ PWR_VGA_CORE_PVCC PWR_VGA_CORE_VCC USBVCCTP
net group POWER_CPU_PLL_10_5: nets 1D8V_EDRAM 1D8V_SIP_S5 1D8V_VCCPGPPF 1V_CPU_XDP_AB 1V_CPU_XDP_CD 1V_DCPDSW 1V_SIP_S5 1V_VCC19P2 1V_VCC24TBT 1V_VCCAMPHYPLL 1V_VCCAPLL 1V_VCCAPLLEBB 1V_VCCDTS 1V_VCCF24NS 1V_VCCF100 1V_VCCF100OC 1V_VCCF135 1V_VCCFHV 1V_VCCFUSEPRG 1V_VCCMPHYAON 1V_VCCSFR 1V_VCCSTG 1V_XDP_S5 3D3V_1D8V_VCCHDA 3D3V_1D8V_VCCPGPPA 3D3V_1D8V_VCCPGPPD 3D3V_1D8V_VCCPSPI 3D3V_VCCPGPPB 3D3V_VCCPGPPC 3D3V_VCCPGPPE 3D3V_VCCPGPPG 3D3V_VCCPRIM 3D3V_VCCPRTCPRIM +VCCPRTC_3P3
net group POWER_RTC_10_10: nets PWR_3D3V_CS2 PWR_3D3V_EN2 V_3P0_BAT_VREG VBAT1 VBAT1_R
net group PWM_10_10: nets 1D2V_VCCSFR_OC 1D2V_VDDQ_CPUCLK 1V1_FB 1V1_POK AD+_G_1 AD+_G_2 AUD_LINK_RST_N_2 BIST_DISABLE_1 BIST_EN DC_IN_D DDR_VTT_CNTL EAPD_DEPOP_2 GPU_1D05V_EN GPU_1D05V_FB_M GPU_1D05V_FB_M1 GPU_1D05V_PG GPU_1D05V_POK GPU_1D05V_VGA_EN GPU_ALLPWR LAN_DISABLE_N_1 LAN_DISABLE_N_2 LED_5VSB NCP81172_FB1 OSD_BIST_N_1 PSYS PWR_1D0V_CS PWR_1D0V_FB PWR_1D0V_RF PWR_2D5V_EN_R PWR_2D5V_FB PWR_2D5V_PG PWR_2V5_EN PWR_3D3V_5V_PG PWR_3D3V_FB2 PWR_5V3V_EMN_R PWR_5V_FB1 PWR_CHG_ACDET PWR_CHG_CMPIN PWR_CHG_CMPIN_R PWR_CHG_CMPIN_RR PWR_CHG_ILIM PWR_CHG_IOUT PWR_CHG_NC PWR_V1P8A_FB PWR_VCCGT_COMP PWR_VCCGT_COMP_R PWR_VCCGT_CSCOMP PWR_VCCGT_CSREF PWR_VCCGT_CSSUM PWR_VCCGT_DIFFOUT PWR_VCCGT_DIFFOUT_R PWR_VCCGT_FB PWR_VCCGT_ILIM PWR_VCCGT_ILIM_NTC PWR_VCCGT_IOUT PWR_VCCGT_TSENSE PWR_VCCGT_TSENSE_NTC PWR_VCCGT_VSN PWR_VCCGT_VSN_G PWR_VCCGT_VSP PWR_VCCSA_COMP PWR_VCCSA_COMP_1 PWR_VCCSA_CSP PWR_VCCSA_CSP_R PWR_VCCSA_ILIM PWR_VCCSA_IOUT PWR_VCCSA_PWM PWR_VCCSA_VSN PWR_VCCSA_VSN_G PWR_VCCSA_VSP_ PWR_VCCSA_VSP_G PWR_VCCSA_VSP_RC PWR_VCORE_COMP PWR_VCORE_COMP_RC PWR_VCORE_CSP PWR_VCORE_CSP_NTC PWR_VCORE_DRON PWR_VCORE_ILIM PWR_VCORE_IOUT PWR_VCORE_TSENSE PWR_VCORE_TSENSE_NTC PWR_VCORE_VRHOT# PWR_VCORE_VSN PWR_VCORE_VSN_G PWR_VCORE_VSP PWR_VCORE_VSP_G PWR_VCORE_VSP_RC PWR_VDDQ_CS PWR_VDDQ_FB PWR_VDDQ_TON PWR_VGA_CORE_COMP PWR_VGA_CORE_COMP_1 PWR_VGA_CORE_EN PWR_VGA_CORE_FBRTN PWR_VGA_CORE_FS PWR_VGA_CORE_PGOOD PWR_VGA_CORE_PSI PWR_VGA_CORE_REFIN PWR_VGA_CORE_SENSE+_1 PWR_VGA_CORE_TALERT# PWR_VGA_CORE_TSNS PWR_VGA_CORE_VID PWR_VGA_CORE_VIDBUF PWR_VGA_CORE_VREF PWR_VGA_CORE_VREF_1 PWR_VGA_CORE_VREF_2 PWR_VGA_VRAM_FB PWR_VGA_VRAM_PFM PWR_VGA_VRAM_POK PWR_VGA_VRAM_SS PWR_VGA_VRAM_TON PWR_VGA_VRAM_VCC PWR_VTT_EN TPM_VSB VREG_PCIAUX_PCH VREG_PCIAUX_PCH_1
net group PWM_20_10: nets AUD_REGREF BQ24737_REGN CBN CBP CPVEE GDI_1V1 GDI_1V1_SCALAR GPU_CLK0_TER GPU_CLK1_TER KBC_VCORF P5P0V PWR_1D0V_BOOT PWR_1D0V_BOOT_R PWR_1D0V_SNB PWR_3D3V_BOOT2 PWR_3D3V_BOOT2_A PWR_3D3V_LDO3 PWR_3D3V_SN PWR_5V_BOOT1 PWR_5V_BOOT1_A PWR_5V_SN PWR_CHG_BTST PWR_CHG_BTST_1 PWR_DDR_SN PWR_VCCGT_BSTA PWR_VCCGT_BSTA_R PWR_VCCGT_BSTB PWR_VCCGT_BSTB_R PWR_VCCGT_SNB1 PWR_VCCGT_SNB2 PWR_VCCSA_BST PWR_VCCSA_BST_RC PWR_VCCSA_SNB PWR_VCORE_BST PWR_VCORE_BST_R PWR_VCORE_SNB PWR_VCORE_VCC PWR_VCORE_VRMP PWR_VDDQ_BOOT PWR_VDDQ_BOOT_A PWR_VDDQ_VDD PWR_VDDQ_VID PWR_VDDQ_VTTREF PWR_VGA_CORE_BOOT1 PWR_VGA_CORE_BOOT1_1 PWR_VGA_CORE_FB PWR_VGA_CORE_LGATE1 PWR_VGA_CORE_SNB PWR_VGA_VRAM_BOOT PWR_VGA_VRAM_BOOT_RC PWR_VGA_VRAM_SNB RTD_REXT TPM_VDD VREF_1
net group PWM_25_20: nets AD+_2 DACA_VDD FB_CAL_PD_VDDQ FB_CAL_PU_GND FB_CAL_TERM_GND FB_PLLAVDD
net group PWM_30_12: nets PWR_CHG_VCC
net group PWM_PHASE: nets PWR_1D0V_LGATE PWR_1D0V_UGATE PWR_3D3V_HG2 PWR_CHG_HIDRV PWR_CHG_LODRV PWR_VCCGT_LGA PWR_VCCGT_LGB PWR_VCCGT_UGA PWR_VCCGT_UGB PWR_VCORE_LG PWR_VCORE_UG PWR_VDDQ_HG PWR_VDDQ_HG_R PWR_VDDQ_LG PWR_VGA_CORE_UGATE1
net group PWR_EN_4-MW: nets +V_1P05_VGA_DISCHIG +V_1P35_VGA_DISCHG DGPU_PWR_EN# DS3_PWRCTL OZ554_ENA PANEL_OFF PANEL_OFF_C PCH_ALW_ON PWR_1D0V_EN PWR_V1P8A_EN PWR_VCORE_EN PWR_VDDQ_EN PWR_VDDQ_EN_R PWR_VTT_EN_R SCALAR_EN SCALAR_EN_G SE_VDDQ_EN SE_VPP_EN SE_VPP_EN_B SE_VTT_EN VCC5_33_CT1 VCC5_33_CT2 VCC5_33_EN VCCSTG_EN VCCSTU_EN VGA_CORE_DISCHG VR_EN
net group PWRGD&RST_4-MW: nets 1P8V_PWR_PG ALL_PWRGD_2 ALL_SYS_PWRGD AMD_RST#_L BATLOW# BP_PWRGD_RST# GPU_PEX_RST_HOLD GPU_PEX_RST_HOLD_GPU# H_CPUPWRGD LAN_DISABLE_N_3 LAN_DISABLE_N_4 LAN_DISABLE_V3 ME_CNTL NGFF_POWER_CTRL_V2 PANEL_ON PCH_DPWROK PCH_PWROK PCH_RTCRST_DOWN PCH_RTCRST_PULLUP PCH_SRTCRSTB_PULLUP PCH_SYSPWROK_G PCH_WAKE_N PCIE_RST# PEX_RST_GPU PEX_RST_GPU_D# PLT_RST#_EC PLT_RST#_TPM PLTRST#_PCH PLTRST*_SIO PLTRST_CR PLTRST_LAN_N PLTRST_N PLTRST_N_1A PLTRST_N_D PLTRST_SL_N PM_PCH_PWROK PM_PWRBTN_N PM_RSMRST_PWRGD_XDP PM_SLP_S3#_R PWR_1D0V_PG PWR_V1P8A_PG PWR_VCORE_VR_RDY PWR_VDDQ_PG PWRBTN_N PWRGD_3V PWROK3_1 Q9637_AB_EC Q9639_AB_EC RSMRST_N RSMRST_PWRGD# SD_WAKE_N SE_BJT_B1 SE_BJT_B2 SE_BJT_B3 SIO_GPU_RST SLP_S3_N SLP_S4_N SLP_S4_N_SIO SLP_S5_N SLP_SUSB SM_DRAMRST# SM_DRAMRST#_R SM_INTRUDER# SUS_PWR_ACK SUS_WARNB SYS_PEX_RST_MON_GPU# SYS_PWROK TP_PMODE_XDP_RST_R_N VCCST_GD_CPU VCCST_GD_R VR_RDY WAKE_N XDP_DBRESET# XDP_DBRESET_XDP# XDP_PREQ# XDP_SYS_PWROK
net group RCOMP: nets CFG_RCOMP CPU_POPIRCOMP EDRAM_OPIO_RCOMP EOPIO_RCOMP PCH_POPIRCOMP XCLK_BIASREF
net group RCOMP_EDP: nets EDP_RCOMP_CPU
net group RCOMP_SM: nets SM_RCOMP_0 SM_RCOMP_1 SM_RCOMP_2
net group RCOMP_UNUSED: nets CSI2_COMP EMMC_RCOMP SD_RCOMP
net group RCOMP_USB-MW: nets USBCOMP
net group SATAHDR_RX_DN0: nets SATA__RXN0_C SATA_RXN0_C_N SATAHDR_RX_DN0
net group SATAHDR_RX_DN1: nets SATA__RXN1_C SATA_RXN1_C_N SATAHDR_RX_DN1
net group SATAHDR_RX_DP0: nets SATA__RXP0_C SATA_RXP0_C_N SATAHDR_RX_DP0
net group SATAHDR_RX_DP1: nets SATA__RXP1_C SATA_RXP1_C_N SATAHDR_RX_DP1
net group SATAHDR_TX_DN0: nets SATA__TXN0_C SATA_TXN0_C_N SATAHDR_TX_DN0
net group SATAHDR_TX_DN1: nets SATA__TXN1_C SATA_TXN1_C_N SATAHDR_TX_DN1
net group SATAHDR_TX_DP0: nets SATA__TXP0_C SATA_TXP0_C_N SATAHDR_TX_DP0
net group SATAHDR_TX_DP1: nets SATA__TXP1_C SATA_TXP1_C_N SATAHDR_TX_DP1
net group SIDE_USB3_TX0+: nets SIDE_USB3_TX0+ USB3_TX0_EMI_DP USB30_TX_CPU_P0
net group SIDE_USB3_TX0-: nets SIDE_USB3_TX0- USB3_TX0_EMI_DN USB30_TX_CPU_N0
net group SIDE_USB3_TX1+: nets SIDE_USB3_TX1+ USB3_TX1_EMI_DP USB30_TX_CPU_P1
net group SIDE_USB3_TX1-: nets SIDE_USB3_TX1- USB3_TX1_EMI_DN USB30_TX_CPU_N1
net group SIO_IT8739-4_5-MW: nets EC_HDMI_PD_N EC_LAN_DISABLE_N IMS SW_ON_N_SIO
net group SMBUS_CLK: nets BATA_SCL_1 CPU_SCALAR_SCL DDPB_CTRL_CLK_CONN HDMI1_CTRL_CLK_CPU HDMI1_SCL HDMI_SCL_IN HDMI_SCL_IN_C I2CC_SCL_PU I2CS_SCL_G ISP_CLK1 NCT_CLK PCH_DVI_CLK RTD_PIN110 RTD_PIN114 SIO_SMCLK0 SMB0_CVT_CLK SML0_CLK SML1_CLK
net group SMBUS_DAT: nets BATA_SDA_1 CPU_SCALAR_SDA DDPB_CTRL_DATA_CONN HDMI1_CTRL_DATA_CPU HDMI1_SDA HDMI_SDA_IN HDMI_SDA_IN_C I2CC_SDA_PU I2CS_SDA_G ISP_DAT1 NCT_DATA PCH_DVI_DATA RTD_PIN111 RTD_PIN115 SIO_SMDAT0 SMB0_CVT_DATA SML0_DATA SML1_DATA
net group SPI-MW: nets CE CE#_1 EC_SPI_CS0# EC_SPI_SI EC_SPI_SO ROM_CS* ROM_CS_R* ROM_SI ROM_SI_R ROM_SO SDIN SDIN_1 SDOUT SO_1 SPI_HOLD_CPU SPI_IO2 SPI_IO3 SPI_MISO SPI_SI_XDP SPI_SO_CPU SPI_WP_CPU SPI_WP_XDP
net group SPI_CLK-MW: nets CLK CLK_1 EC_SPI_CLK ROM_SCLK ROM_SCLK_R
net group SVID-MW: nets PWR_VCORE_ALERT# PWR_VCORE_SCLK PWR_VCORE_SDIO VIDALERT#_CPU VIDALERT#_CPU_R VIDSCK_CPU VIDSCK_CPU_R VIDSOUT_CPU VIDSOUT_CPU_R
net group TP-MW: nets AC_IN_KBC# CATERR#_CPU CPU_A16_TP CPU_A17_TP CPU_B16_TP CPU_B17_TP CPU_C18_TP CPU_C19_TP CPU_D4_TP CPU_D5_TP GPP_B2/VRALERT# LPCPD_TPM PP_TPM RSVD_TP_AK12 RSVD_TP_AK13 RSVD_TP_BA68 RSVD_TP_BA70 RSVD_TP_BB68 RSVD_TP_BB69 RSVD_TP_F65 RSVD_TP_G65 SLP_A_N SLP_LAN_N SLP_S0_N TP1_AY4 TP2_BB3 TP4_BB5 TP5_AU5 TP6_AT5 TP_DDPC_CTRLDATA TP_L_BKLTEN TP_L_VDDEN TP_NGFF_COEX1 TP_NGFF_COEX2 TP_NGFF_COEX3 TP_NGFF_LED1 TP_NGFF_LED2 TP_NGFF_MLDIR TPA3131_SYNC V0.85A_VID0 V0.85A_VID1 VCCCOREG0 VCCCOREG1
net group UART-MW: nets LPSS_UART2_RXD LPSS_UART2_TXD SIO_UART1_RX SIO_UART1_TX
net group WLAN_CLINK_4_10-MW: nets CLINK_CLK_LAN CLINK_DATA_LAN CLINK_RST_LAN_N
net group XDP-MW: nets PCH_JTAG_TCK PCH_JTAG_TDI PCH_JTAG_TDO PCH_JTAG_TMS XDP_PRDY# XDP_PRSENT_PIN60 XDP_PRSNT_PIN1 XDP_TCK_JTAGX XDP_TCLK XDP_TCLK1 XDP_TDI XDP_TDO XDP_TDO_CPU XDP_TMS XDP_TRST#
nets with their own width: min track width 0.305; nets VCC_FAN

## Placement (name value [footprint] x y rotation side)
AFTP1  -  [TPAD28]  35.09 59.44 0 top
BAT2  ACES-CON9-10-GP  [51202-00901-W01-U]  26 64.14 270 top
BT1  BAT-AAA-BAT-034-K01-GP  [AAA-BAT-034-K01]  96.8 56.14 0 top
C1  SCD1U16V2KX-3DLGP  [C402H22]  19.85 224.66 180 top
C2  SCD1U16V2KX-3DLGP  [C402H22]  30.94 224.18 180 top
C3  SCD1U16V2KX-3DLGP  [C402H22]  45.37 224.03 180 top
C4  SC2D2U10V3KX-1DLGP-U  [C603H36]  124.24 223.9 180 top
C5  SCD1U16V2KX-3-LL-GP  [C402H22]  79.54 220.22 90 top
C6  SCD1U16V2KX-3DLGP  [C402H22]  121.95 205.74 180 top
C7  SC10U6D3V3MX-DL-GP  [C603H36]  123.1 205.74 180 top
C8  SC10U6D3V3MX-DL-GP  [C603H36]  124.37 205.74 180 top
C9  SC10U6D3V3MX-DL-GP  [C603H36]  16.42 197.1 90 top
C10  SC1U50V3KX-1-GP  [C603H36]  16.42 195.83 90 top
C11  SCD1U16V2KX-3DLGP  [C402H22]  160.18 195.45 270 top
C12  SC1U10V2KX-1DLGP  [C402H22]  79.92 195.33 180 top
C13  SC1U10V2KX-1DLGP  [C402H22]  80.93 195.33 180 top
C14  SC10U10V5KX-2DLGP  [C805H50]  16.92 194.18 90 top
C15  SC10U10V5KX-2DLGP  [C805H50]  160.18 194.06 270 top
C16  SCD1U16V2KX-3DLGP  [C402H22]  66.45 192.15 270 top
C17  SC10U10V5KX-2DLGP  [C805H50]  160.18 192.02 270 top
C18  SC1U10V2KX-1DLGP  [C402H22]  158.66 181.61 90 top
C19  SC1U10V2KX-1DLGP  [C402H22]  56.68 175.64 180 top
C20  SC1U10V2KX-1DLGP  [C402H22]  60.74 175.64 180 top
C21  SCD01U50V2KX-1DLGP  [C402H22]  14 174.33 270 top
C22  SCD01U50V2KX-1DLGP  [C402H22]  14 173.44 270 top
C23  SC22U6D3V3MX-1-DL-GP  [C603H40]  42.96 171.2 180 top
C24  SCD01U50V2KX-1DLGP  [C402H22]  14 170.9 270 top
C25  SCD01U50V2KX-1DLGP  [C402H22]  14 170.01 270 top
C26  SC22U6D3V3MX-1-DL-GP  [C603H40]  54.8 162.97 0 top
C27  SC33P50V2JN-3DLGP  [C402H22]  64.42 159.38 0 top
C28  SCD1U16V2KX-3DLGP  [C402H22]  67.98 158.5 90 top
C29  SCD1U16V2KX-3DLGP  [C402H22]  67.98 157.61 90 top
C30  SC33P50V2JN-3DLGP  [C402H22]  64.93 156.77 90 top
C31  SCD22U10V2KX-2-GP  [C402H22]  60.1 150.5 180 top
C32  SCD22U10V2KX-2-GP  [C402H22]  60.99 150.5 180 top
C33  SCD1U16V2KX-3DLGP  [C402H22]  62.39 150.5 180 top
C34  SCD1U16V2KX-3DLGP  [C402H22]  63.28 150.5 180 top
C35  SC1U10V2KX-1DLGP  [C402H22]  100.87 150.5 0 top
C36  SCD1U16V2KX-3DLGP  [C402H22]  101.76 150.5 180 top
C37  SC1U10V2KX-1DLGP  [C402H22]  102.52 148.84 270 top
C38  SCD22U10V2KX-2-GP  [C402H22]  63.03 148.21 90 top
C39  SC1U10V2KX-1DLGP  [C402H22]  68.23 148.21 180 top
C40  SCD01U50V2KX-1DLGP  [C402H22]  17.23 147.37 270 top
C41  SCD01U50V2KX-1DLGP  [C402H22]  17.23 146.48 270 top
C42  SCD1U16V2KX-3DLGP  [C402H22]  102.52 147.96 270 top
C43  SCD1U16V2KX-3DLGP  [C402H22]  98.84 147.47 0 top
C44  SCD22U10V2KX-2-GP  [C402H22]  63.03 147.32 90 top
C45  SCD1U16V2KX-3DLGP  [C402H22]  102.52 147.07 270 top
C46  SCD22U10V2KX-2-GP  [C402H22]  63.03 146.3 90 top
C47  SCD22U10V2KX-2-GP  [C402H22]  63.03 145.41 90 top
C48  SC4D7U6D3V3KX-DLGP  [C603H36]  43.09 144.15 180 top
C49  SCD22U10V2KX-2-GP  [C402H22]  63.03 143.89 90 top
C50  SCD22U10V2KX-2-GP  [C402H22]  63.03 143 90 top
C51  SC1U10V2KX-1DLGP  [C402H22]  88.43 141.53 270 top
C52  SCD01U50V2KX-1DLGP  [C402H22]  17.43 140.59 270 top
C53  SCD01U50V2KX-1DLGP  [C402H22]  17.43 139.7 270 top
C54  SC4D7U6D3V3KX-DLGP  [C603H36]  57.82 141.35 0 top
C55  SC1U10V2KX-1DLGP  [C402H22]  77.76 141.35 90 top
C56  SC10U6D3V2MX-2-GP  [C402-TO0D2H28]  56.29 140.34 90 top
C57  SC1U10V2KX-1DLGP  [C402H22]  52.87 139.83 0 top
C58  SC100P50V2JN-3DLGP  [C402H22]  74.71 139.7 90 top
C59  SC1U10V2KX-1DLGP  [C402H22]  56.34 139.32 90 top
C60  SC22U6D3V5MX-2DLGP  [C805H54]  42.07 138.68 0 top
C61  SC22U6D3V5MX-2DLGP  [C805H54]  44.23 138.68 0 top
C62  SC22U6D3V5MX-2DLGP  [C805H54]  46.26 138.68 0 top
C63  SC1U10V2KX-1DLGP  [C402H22]  70.01 138.43 270 top
C64  SC47U4V3MX-1-GP  [C603H40]  55.66 138.3 90 top
C65  SC10U6D3V2MX-2-GP  [C402-TO0D2H28]  48.8 137.92 0 top
C66  SC1U10V2KX-1DLGP  [C402H22]  52.87 137.92 180 top
C67  SC1U10V2KX-1DLGP  [C402H22]  81.06 137.29 180 top
C68  SC1U10V2KX-1DLGP  [C402H22]  84.11 136.91 90 top
C69  SC1U10V2KX-1DLGP  [C402H22]  79.54 132.97 90 top
C70  SC3D3P50V2CN-DL-GP  [C402H22]  90.58 132.97 180 top
C71  SC3D3P50V2CN-DL-GP  [C402H22]  90.58 131.06 0 top
C72  SCD1U16V2KX-3DLGP  [C402H22]  98.48 128.73 0 top
C73  SC1U10V2KX-1DLGP  [C402H22]  99.35 128.73 0 top
C74  SCD1U16V2KX-3DLGP  [C402H22]  161.45 124.84 90 top
C75  SC10U10V5KX-2DLGP  [C805H50]  166.15 119.76 0 top
C76  SC10U10V5KX-2DLGP  [C805H50]  168.18 119.76 0 top
C77  SCD1U16V2KX-3DLGP  [C402H22]  169.58 119.76 0 top
C78  SCD1U25V2KX-1-DL-GP  [C402H22]  150.15 119.63 270 top
C79  SC1KP50V2KX-1DLGP  [C402H22]  162.21 119.38 90 top
C80  SCD1U16V2KX-3DLGP  [C402H22]  46.39 118.49 90 top
C81  SCD1U16V2KX-3DLGP  [C402H22]  160.43 116.71 90 top
C82  SCD1U16V2KX-3DLGP  [C402H22]  160.43 115.82 90 top
C84  SCD01U50V2KX-1DLGP  [C402H22]  95.28 114.55 180 top
C85  SCD1U16V2KX-3DLGP  [C402H22]  47.91 113.16 180 top
C86  SC470P50V2KX-3DLGP  [C402H22]  164.75 111.51 180 top
C87  SC820P50V2KX-1-DL-GP  [C402H22]  47.28 110.62 270 top
C88  SC820P50V2KX-1-DL-GP  [C402H22]  47.28 109.73 270 top
C89  SC22U6D3V5MX-2DLGP  [C805H54]  98.08 107.31 180 top
C90  SC22U6D3V5MX-2DLGP  [C805H54]  100.11 107.31 180 top
C91  SC22U6D3V5MX-2DLGP  [C805H54]  102.14 107.31 180 top
C92  SC22U6D3V5MX-2DLGP  [C805H54]  104.17 107.31 180 top
C93  SCD1U16V2KX-3DLGP  [C402H22]  47.79 106.3 0 top
C94  SCD1U16V2KX-3DLGP  [C402H22]  175.67 105.66 180 top
C95  SCD1U16V2KX-3DLGP  [C402H22]  102.9 99.44 0 top
C96  SC47U6D3V5MX-1DL-GP  [C805H54]  99.98 99.57 0 top
C97  SC10U6D3V3MX-DL-GP  [C603H36]  101.63 99.44 0 top
C98  SC22U6D3V5MX-2DLGP  [C805H54]  97.57 103.12 180 top
C99  SCD1U16V2KX-3DLGP  [C402H22]  99.22 102.74 180 top
C100  SCD1U16V2KX-3DLGP  [C402H22]  160.05 97.66 90 top
C101  SCD1U16V2KX-3DLGP  [C402H22]  160.05 96.77 90 top
C102  SCD1U16V2KX-3DLGP  [C402H22]  47.99 96.29 0 top
C103  SC1U10V2KX-1DLGP  [C402H22]  136.69 95.12 270 top
C104  SC22U6D3V5MX-2DLGP  [C805H54]  111.16 93.98 180 top
C105  SCD1U16V2KX-3DLGP  [C402H22]  47.99 94.39 180 top
C106  SC100P50V2JN-3DLGP  [C402H22]  99.47 87.12 0 top
C107  SC15P50V2JN-DL-GP  [C402H22]  85.89 85.47 270 top
C108  SC15P50V2JN-DL-GP  [C402H22]  87.79 85.47 90 top
C109  SC10U10V5KX-2DLGP  [C805H50]  162.95 84.71 270 top
C110  SC10U10V5KX-2DLGP  [C805H50]  166.53 84.45 90 top
C111  SC10U10V5KX-2DLGP  [C805H50]  158.25 83.69 180 top
C112  SC10U10V5KX-2DLGP  [C805H50]  160.18 83.69 180 top
C113  SCD1U16V2KX-3DLGP  [C402H22]  163.23 83.31 90 top
C114  SC1U50V3KX-1-GP  [C603H36]  64.55 82.68 90 top
C115  SC10U10V5KX-2DLGP  [C805H50]  166.02 82.42 90 top
C116  SC100P50V2JN-3DLGP  [C402H22]  172.63 82.42 0 top
C117  SC1KP50V2KX-1DLGP  [C402H22]  56.29 82.3 0 top
C118  SCD1U16V2KX-3DLGP  [C402H22]  62.64 82.3 0 top
C119  SC2D2U10V3KX-1DLGP-U  [C603H36]  162.49 82.3 270 top
C120  SC10U6D3V3MX-DL-GP  [C603H36]  61.63 81.92 0 top
C121  SC1U50V3KX-1-GP  [C603H36]  64.55 81.41 90 top
C122  SC10U10V5KX-2DLGP  [C805H50]  169.58 81.41 90 top
C123  SCD1U16V2KX-3DLGP  [C402H22]  165.26 81.03 270 top
C124  SCD01U50V2KX-1DLGP  [C402H22]  59.98 80.9 270 top
C125  SCD1U25V2KX-1-DL-GP  [C402H22]  156.88 79.76 0 top
C126  SC10U10V5KX-2DLGP  [C805H50]  169.63 79.4 90 top
C127  SCD1U16V2KX-3DLGP  [C402H22]  69.76 77.72 180 top
C128  SC100P50V2JN-3DLGP  [C402H22]  170.98 77.47 180 top
C129  SC22P50V2JN-4DLGP  [C402H22]  156.24 77.09 90 top
C130  SCD1U16V2KX-3-LL-GP  [C402H22]  80.04 76.83 90 top
C131  SC1U10V2KX-1DLGP  [C402H22]  58.45 76.2 180 top
C132  SC1U10V2KX-1DLGP  [C402H22]  59.34 76.2 180 top
C133  SC2200P50V2KX-2DLGP  [C402H22]  147.99 76.2 270 top
C134  SC1U10V2KX-1DLGP  [C402H22]  152.43 76.07 90 top
C135  SC100P50V2JN-3DLGP  [C402H22]  170.98 75.31 0 top
C136  SC10U6D3V3MX-DL-GP  [C603H36]  155.86 74.93 270 top
C137  SC100P50V2JN-3DLGP  [C402H22]  170.98 73.41 0 top
C138  SCD1U16V2KX-3DLGP  [C402H22]  158.02 73.28 0 top
C139  SCD1U16V2KX-3DLGP  [C402H22]  152.94 73.15 180 top
C140  SC10U6D3V3MX-DL-GP  [C603H36]  153.96 72.9 180 top
C141  SC10U6D3V3MX-DL-GP  [C603H36]  157.01 72.9 0 top
C142  SCD1U16V2KX-3DLGP  [C402H22]  164.5 71.25 90 top
C143  SCD1U16V2KX-3DLGP  [C402H22]  167.29 71.25 90 top
C144  SC1U10V2KX-1DLGP  [C402H22]  162.21 70.61 0 top
C145  SC10U6D3V3MX-DL-GP  [C603H36]  164.5 70.23 270 top
C146  SC10U6D3V3MX-DL-GP  [C603H36]  167.29 70.23 90 top
C147  SCD1U16V2KX-3DLGP  [C402H22]  79.92 70.1 90 top
C148  SC100P50V2JN-3DLGP  [C402H22]  158.15 70.05 0 top
C149  SC22U6D3V5MX-2DLGP  [C805H54]  96.05 69.09 0 top
C150  SC10U25V5KX-DL-GP  [C805H58]  98.08 69.09 0 top
C151  SC4D7U6D3V3KX-DLGP  [C603H36]  93.12 68.83 180 top
C152  SC1U50V3KX-1-GP  [C603H36]  94.39 68.83 0 top
C153  SCD01U25V2KX-3DLGP  [C402H22]  84.74 68.71 180 top
C154  SC1U50V3KX-1-GP  [C603H36]  164.5 68.07 270 top
C155  SC100P50V2JN-3DLGP  [C402H22]  156.75 67.97 90 top
C156  SCD1U16V2KX-3DLGP  [C402H22]  72.8 67.18 270 top
C157  SCD1U16V2KX-3DLGP  [C402H22]  158.78 66.55 0 top
C158  SCD1U16V2KX-3DLGP  [C402H22]  72.8 66.29 270 top
C159  SC10U6D3V3MX-DL-GP  [C603H36]  157.69 66.19 0 top
C160  SCD1U16V2KX-3DLGP  [C402H22]  72.8 65.41 270 top
C161  SCD1U16V2KX-3DLGP  [C402H22]  153.7 64.64 0 top
C162  SC1U10V2KX-1DLGP  [C402H22]  154.59 64.64 0 top
C163  SCD1U16V2KX-3DLGP  [C402H22]  72.8 64.52 270 top
C164  SCD1U16V2KX-3DLGP  [C402H22]  126.78 63.88 270 top
C165  SCD1U16V2KX-3DLGP  [C402H22]  72.8 63.63 270 top
C166  SCD1U16V2KX-3DLGP  [C402H22]  72.8 62.74 270 top
C167  SCD1U16V2KX-3DLGP  [C402H22]  124.49 62.66 0 top
C168  SCD1U16V2KX-3DLGP  [C402H22]  125.38 62.66 0 top
C169  SCD1U16V2KX-3DLGP  [C402H22]  72.8 61.72 270 top
C170  SCD1U16V2KX-3DLGP  [C402H22]  72.8 60.83 270 top
C171  SCD1U16V2KX-3DLGP  [C402H22]  124.49 60.76 180 top
C172  SCD1U16V2KX-3DLGP  [C402H22]  125.38 60.76 180 top
C173  SCD1U16V2KX-3DLGP  [C402H22]  160.18 59.69 0 top
C174  SC1U10V2KX-1DLGP  [C402H22]  157.64 58.29 270 top
C175  SC1U10V2KX-1DLGP  [C402H22]  161.07 58.29 90 top
C176  SCD027U50V3KX-DL-GP  [C603H36]  166.43 56.69 0 top
C177  SC1U50V3KX-1-GP  [C603H36]  160.69 56.52 0 top
C178  SC1U50V3KX-1-GP  [C603H36]  161.86 56.52 0 top
C179  SCD027U50V3KX-DL-GP  [C603H36]  164.5 56.18 270 top
C180  SCD027U50V3KX-DL-GP  [C603H36]  157.13 55.24 0 top
C181  SCD027U50V3KX-DL-GP  [C603H36]  158.4 55.24 0 top
C182  SC1U10V2KX-1DLGP  [C402H22]  148.37 54.86 90 top
C183  SC100P50V2JN-3DLGP  [C402H22]  155.48 54.61 90 top
C184  SC15P50V2JN-DL-GP  [C402H22]  67.11 53.21 180 top
C185  SC1KP50V2KX-1DLGP  [C402H22]  165.39 51.69 180 top
C186  SC15P50V2JN-DL-GP  [C402H22]  67.11 51.28 0 top
C187  SCD1U16V2KX-3DLGP  [C402H22]  73.31 51.05 270 top
C188  SCD1U50V3KX-DL-GP  [C603H35]  154.24 50.93 180 top
C189  SCD1U16V2KX-3DLGP  [C402H22]  73.31 50.16 270 top
C190  SCD1U16V2KX-3DLGP  [C402H22]  122.72 49.91 270 top
C191  SCD1U10V2KX-5GP  [C402H22]  126.4 49.53 0 top
C192  SCD1U50V3KX-DL-GP  [C603H35]  165.13 49.4 180 top
C193  SC10U25V5KX-DL-GP  [C805H58]  152.81 47.5 0 top
C194  SCD1U50V3KX-DL-GP  [C603H35]  154.47 47.5 0 top
C195  SCD1U16V2KX-3DLGP  [C402H22]  131.48 47.24 90 top
C196  SC2D2U10V3KX-1DLGP-U  [C603H36]  131.22 46.23 90 top
C197  SC10U25V5KX-DL-GP  [C805H58]  164.63 46.23 0 top
C198  SCD1U16V2KX-3DLGP  [C402H22]  135.16 45.47 0 top
C199  SC100P50V2JN-3GP  [C402H22]  136.05 45.47 0 top
C200  SC220P50V2KX-3GP  [C402H22]  132.62 45.21 270 top
C201  SCD22U25V3KX-DL-GP  [C603H36]  153.96 42.67 90 top
C202  SCD22U25V3KX-DL-GP  [C603H36]  156.62 42.67 270 top
C203  SCD22U25V3KX-DL-GP  [C603H36]  160.43 42.67 90 top
C204  SCD22U25V3KX-DL-GP  [C603H36]  163.23 42.67 270 top
C205  SCD1U16V2KX-3DLGP  [C402H22]  146.72 42.55 270 top
C206  SCD68U16V3KX-4-GP  [C603H36]  153.96 41.4 270 top
C207  SCD68U16V3KX-4-GP  [C603H36]  156.62 41.4 90 top
C208  SCD68U16V3KX-4-GP  [C603H36]  160.43 41.4 270 top
C209  SCD68U16V3KX-4-GP  [C603H36]  163.23 41.4 90 top
C210  SCD1U16V2KX-3DLGP  [C402H22]  135.03 41.15 180 top
C211  SCD01U50V2KX-1DLGP  [C402H22]  135.92 41.15 180 top
C212  SCD01U50V2KX-1DLGP  [C402H22]  130.34 41.02 270 top
C213  SCD01U50V2KX-1DLGP  [C402H22]  130.34 40.13 270 top
C214  SCD1U16V2KX-3DLGP  [C402H22]  136.56 39.62 90 top
C215  SCD1U16V2KX-3DLGP  [C402H22]  139.35 38.86 270 top
C216  SC100P50V2JN-3DLGP  [C402H22]  82.96 38.73 270 top
C217  SC100P50V2JN-3DLGP  [C402H22]  85 38.73 90 top
C218  SCD1U25V3ZY-1-LL-GP  [C603H36]  48.42 38.23 0 top
C219  SCD1U16V2KX-3DLGP  [C402H22]  139.35 37.97 270 top
C220  SCD1U16V2KX-3DLGP  [C402H22]  139.35 37.08 270 top
C221  SCD1U16V2KX-3DLGP  [C402H22]  139.35 36.2 270 top
C222  SC10U25V5KX-DL-GP  [C805H58]  45.37 35.69 90 top
C223  SCD1U16V2KX-3DLGP  [C402H22]  139.35 35.31 270 top
C224  SC1KP50V2KX-1DLGP  [C402H22]  153.07 35.31 270 top
C225  SC1KP50V2KX-1DLGP  [C402H22]  155.99 35.31 90 top
C226  SC1KP50V2KX-1DLGP  [C402H22]  159.04 35.31 270 top
C227  SC1KP50V2KX-1DLGP  [C402H22]  162.09 35.31 90 top
C228  SCD1U16V2KX-3DLGP  [C402H22]  139.35 34.42 270 top
C229  SC10U25V5KX-DL-GP  [C805H58]  45.32 33.43 90 top
C230  SCD1U16V2KX-3DLGP  [C402H22]  139.35 33.27 270 top
C231  SCD1U50V3KX-DL-GP  [C603H35]  69.76 33.02 90 top
C232  SCD1U16V2KX-3DLGP  [C402H22]  139.35 32.38 270 top
C233  SCD1U16V2KX-3DLGP  [C402H22]  136.81 31.65 0 top
C234  SCD1U16V2KX-3DLGP  [C402H22]  83.22 31.62 180 top
C235  SCD1U16V2KX-3DLGP  [C402H22]  129.32 31.6 270 top
C236  SCD1U16V2KX-3DLGP  [C402H22]  30.13 30.35 180 top
C237  SCD1U16V2KX-3DLGP  [C402H22]  127.92 30.1 180 top
C238  SCD1U16V2KX-3DLGP  [C402H22]  75.73 29.84 180 top
C239  SC2D2U10V3KX-1DLGP-U  [C603H36]  74.58 29.46 180 top
C240  SC1U50V3KX-1-GP  [C603H36]  69.12 29.21 90 top
C241  SCD1U16V2KX-3DLGP  [C402H22]  105.19 28.83 270 top
C242  SC100P50V2JN-3DLGP  [C402H22]  36.13 28.47 0 top
C243  SC10U10V5KX-2DLGP  [C805H50]  39.91 28.7 90 top
C244  SCD01U50V2KX-1DLGP  [C402H22]  39.4 27.3 270 top
C245  SCD01U50V2KX-1DLGP  [C402H22]  39.4 25.27 270 top
C246  SCD1U16V2KX-3DLGP  [C402H22]  33.31 25.02 90 top
C247  SCD1U25V2KX-1-DL-GP  [C402H22]  37.12 24.77 180 top
C248  SCD1U25V2KX-1-DL-GP  [C402H22]  38.01 24.77 180 top
C249  SC1KP50V2KX-1DLGP  [C402H22]  39.4 24.38 270 top
C250  SCD1U16V2ZY-2DLGP  [C402H22]  120.05 23.62 90 top
C251  SCD1U16V2KX-3DLGP  [C402H22]  41.82 23.11 0 top
C252  SC27P50V2JN-2DLGP  [C402H22]  42.71 23.11 0 top
C253  SCD1U16V2ZY-2DLGP  [C402H22]  127.67 20.07 90 top
C254  SC33P50V2JN-3DLGP  [C402H22]  124.11 19.05 270 top
C255  SC4D7U6D3V3KX-DLGP  [C603H36]  46.26 17.14 270 top
C256  SCD01U50V2KX-1DLGP  [C402H22]  49.82 17.78 180 top
C257  SCD1U16V2KX-3DLGP  [C402H22]  30.51 16.38 270 top
C258  SC4D7U6D3V3KX-DLGP  [C603H36]  46.26 15.88 270 top
C259  SCD1U16V2KX-3DLGP  [C402H22]  30.51 15.37 270 top
C260  SC4D7U6D3V3KX-DLGP  [C603H36]  46.26 14.61 270 top
C261  SC10U10V5KX-2DLGP  [C805H50]  90.2 13.59 270 top
C262  SCD1U16V2KX-3DLGP  [C402H22]  33.43 13.46 180 top
C263  SC10U10V5KX-2DLGP  [C805H50]  123.73 12.32 270 top
C264  SC10U10V5KX-2DLGP  [C805H50]  90.2 11.56 270 top
C265  SCD1U16V2KX-3DLGP  [C402H22]  41.44 11.38 90 top
C266  SC10P50V2JN-4DLGP  [C402H22]  30.77 11.18 270 top
C267  SC10P50V2JN-4DLGP  [C402H22]  32.67 11.18 90 top
C268  SCD1U16V2KX-3DLGP  [C402H22]  123.1 10.92 270 top
C269  SCD1U16V2KX-3DLGP  [C402H22]  34.32 10.67 0 top
C270  SC15P50V2JN-DL-GP  [C402H22]  35.72 10.29 270 top
C271  SC1KP50V2KX-1DLGP  [C402H22]  93.51 10.29 90 top
C272  SCD1U16V2KX-3DLGP  [C402H22]  90.33 10.16 270 top
C273  SC1KP50V2KX-1DLGP  [C402H22]  123.1 10.03 270 top
C274  SC1U10V2KX-1DLGP  [C402H22]  128.3 9.91 270 top
C275  SC2D2U10V3KX-1DLGP-U  [C603H36]  43.85 9.53 270 top
C276  SC15P50V2JN-DL-GP  [C402H22]  39.15 9.4 90 top
C277  SC1KP50V2KX-1DLGP  [C402H22]  123.1 9.14 270 top
C278  SC10U10V5KX-2DLGP  [C805H50]  122.97 6.86 180 top
C279  SC1U10V2KX-1DLGP  [C402H22]  39.66 5.97 0 top
C280  SC1U10V2KX-1DLGP  [C402H22]  45.25 5.97 0 top
C281  SCD1U16V2KX-3DLGP  [C402H22]  126.02 4.57 90 top
C282  SC1U10V2KX-1DLGP  [C402H22]  127.92 4.57 270 top
C283  SCD1U16V2KX-3DLGP  [C402H22]  21.24 224.92 0 bottom
C284  SCD1U16V2KX-3DLGP  [C402H22]  25.43 224.41 0 bottom
C285  SC10U25V5KX-DL-GP  [C805H58]  8.42 214.5 0 bottom
C286  SC1U6D3V2KX-GP  [C402H22]  79.79 212.09 90 bottom
C287  SC1U6D3V2KX-GP  [C402H22]  124.75 211.58 90 bottom
C288  SCD1U16V2KX-3DLGP  [C402H22]  124.75 209.55 90 bottom
C289  SC1U6D3V2KX-GP  [C402H22]  122.72 208.28 0 bottom
C290  SC1U10V2KX-1DLGP  [C402H22]  153.32 206.88 270 bottom
C291  SC2D2U10V3KX-1DLGP-U  [C603H36]  146.46 205.99 90 bottom
C292  SC1U10V2KX-1DLGP  [C402H22]  144.18 205.99 270 bottom
C293  SCD1U16V2KX-3DLGP  [C402H22]  146.46 204.98 90 bottom
C294  SCD1U16V2KX-3DLGP  [C402H22]  79.28 198.5 270 bottom
C295  SCD022U16V2KX-3DLGP  [C402H22]  92.24 184.91 90 bottom
C296  SC1U10V2KX-1DLGP  [C402H22]  83.09 184.4 90 bottom
C297  SC1U10V2KX-1DLGP  [C402H22]  146.46 184.28 270 bottom
C298  SC1U10V2KX-1DLGP  [C402H22]  81.44 183.39 90 bottom
C299  SC1U10V2KX-1DLGP  [C402H22]  79.54 182.75 90 bottom
C300  SC1U10V2KX-1DLGP  [C402H22]  83.22 182.5 270 bottom
C301  SC10U6D3V3MX-DL-GP  [C603H36]  106.84 181.99 90 bottom
C302  SC1U10V2KX-1DLGP  [C402H22]  79.54 181.86 90 bottom
C303  SC1U10V2KX-1DLGP  [C402H22]  81.44 181.36 90 bottom
C304  SC1U10V2KX-1DLGP  [C402H22]  83.35 180.72 270 bottom
C305  SC1U10V2KX-1DLGP  [C402H22]  81.44 179.71 90 bottom
C306  SC10U6D3V3MX-DL-GP  [C603H36]  106.84 179.45 90 bottom
C307  SC1U10V2KX-1DLGP  [C402H22]  152.56 178.31 270 bottom
C308  SC10U6D3V3MX-DL-GP  [C603H36]  106.84 178.18 90 bottom
C309  SC10U6D3V3MX-DL-GP  [C603H36]  95.41 175.9 0 bottom
C310  SCD1U16V2KX-3DLGP  [C402H22]  47.79 175.13 90 bottom
C311  SC22U6D3V5MX-2-LL-GP  [C805H54]  146.34 175.01 0 bottom
C312  SC22U6D3V5MX-2-LL-GP  [C805H54]  131.1 175.01 0 bottom
C313  SC1U10V2KX-1DLGP  [C402H22]  72.85 174.62 0 bottom
C314  SC1U10V2KX-1DLGP  [C402H22]  93.25 173.35 90 bottom
C315  SC10U6D3V3MX-DL-GP  [C603H36]  93.25 171.45 90 bottom
C316  SC22U6D3V5MX-2-LL-GP  [C805H54]  139.35 170.43 0 bottom
C317  SC1U10V2KX-1DLGP  [C402H22]  72.55 169.29 270 bottom
C318  SC1U10V2KX-1DLGP  [C402H22]  76.61 168.91 0 bottom
C319  SC1U10V2KX-1DLGP  [C402H22]  92.44 168.71 180 bottom
C320  SC10U6D3V2MX-2-GP  [C402-TO0D2H28]  93.35 168.66 180 bottom
C321  SC1U10V2KX-1DLGP  [C402H22]  87.41 168.53 0 bottom
C322  SC1U10V2KX-1DLGP  [C402H22]  72.55 168.4 270 bottom
C323  SC22U6D3V5MX-2-LL-GP  [C805H54]  154.47 168.28 180 bottom
C324  SC22U6D3V3MX-1-DL-GP  [C603H40]  84.87 167.41 0 bottom
C325  SC22U6D3V3MX-1-DL-GP  [C603H40]  83.7 167.41 0 bottom
C326  SC22U6D3V3MX-1-DL-GP  [C603H40]  82.53 167.41 0 bottom
C327  SC22U6D3V3MX-1-DL-GP  [C603H40]  81.36 167.41 0 bottom
C328  SC22U6D3V3MX-1-DL-GP  [C603H40]  80.2 167.41 0 bottom
C329  SC22U6D3V3MX-1-DL-GP  [C603H40]  79.03 167.41 0 bottom
C330  SC1U10V2KX-1DLGP  [C402H22]  138.97 167.39 180 bottom
C331  SC1U10V2KX-1DLGP  [C402H22]  93.63 166.75 0 bottom
C332  SC1U10V2KX-1DLGP  [C402H22]  71.03 166.75 90 bottom
C333  SC1U10V2KX-1DLGP  [C402H22]  91.35 166.24 90 bottom
C334  SCD1U16V2KX-3DLGP  [C402H22]  139.48 165.99 90 bottom
C335  SC1U10V2KX-1DLGP  [C402H22]  87.79 164.97 270 bottom
C336  SC1U10V2KX-1DLGP  [C402H22]  87.79 164.08 270 bottom
C337  SCD1U16V2KX-3DLGP  [C402H22]  154.59 163.7 270 bottom
C338  SCD1U16V2KX-3DLGP  [C402H22]  146.46 163.7 90 bottom
C339  SCD1U16V2KX-3DLGP  [C402H22]  131.22 163.45 90 bottom
C340  SC1U10V2KX-1DLGP  [C402H22]  87.79 163.22 270 bottom
C341  SC10U6D3V3MX-DL-GP  [C603H36]  94.27 162.94 90 bottom
C342  SC1U10V2KX-1DLGP  [C402H22]  76.11 162.94 180 bottom
C343  SCD1U16V2KX-3DLGP  [C402H22]  146.46 162.81 90 bottom
C344  SC1U10V2KX-1DLGP  [C402H22]  87.13 162.36 270 bottom
C345  SC1U10V2KX-1DLGP  [C402H22]  74.71 162.31 270 bottom
C346  SCD1U16V2KX-3DLGP  [C402H22]  131.22 161.93 90 bottom
C347  SC1U10V2KX-1DLGP  [C402H22]  90.2 161.54 90 bottom
C348  SC1U10V2KX-1DLGP  [C402H22]  87.79 161.42 270 bottom
C349  SC1U10V2KX-1DLGP  [C402H22]  154.59 161.29 270 bottom
C350  SC22U6D3V3MX-1-DL-GP  [C603H40]  84.28 161.16 0 bottom
C351  SC22U6D3V3MX-1-DL-GP  [C603H40]  83.12 161.16 0 bottom
C352  SC22U6D3V3MX-1-DL-GP  [C603H40]  79.61 161.16 0 bottom
C353  SC22U6D3V3MX-1-DL-GP  [C603H40]  78.44 161.16 0 bottom
C354  SC1U10V2KX-1DLGP  [C402H22]  76.11 161.04 0 bottom
C355  SCD1U16V2KX-3DLGP  [C402H22]  131.22 160.53 90 bottom
C356  SCD1U16V2KX-3DLGP  [C402H22]  146.46 159.38 90 bottom
C357  SC1U10V2KX-1DLGP  [C402H22]  90.89 159.13 180 bottom
C358  SC22U6D3V3MX-1-DL-GP  [C603H40]  131.1 158.75 90 bottom
C359  SCD1U16V2KX-3DLGP  [C402H22]  154.59 158.62 270 bottom
C360  SCD1U16V2KX-3DLGP  [C402H22]  139.35 158.62 270 bottom
C361  SC1U10V2KX-1DLGP  [C402H22]  146.46 158.37 90 bottom
C362  SC1U10V2KX-1DLGP  [C402H22]  73.31 157.99 270 bottom
C363  SCD1U16V2KX-3DLGP  [C402H22]  154.59 157.73 270 bottom
C364  SC1U10V2KX-1DLGP  [C402H22]  139.35 157.73 270 bottom
C365  SC1U10V2KX-1DLGP  [C402H22]  82.84 156.97 0 bottom
C366  SC22U6D3V3MX-1-DL-GP  [C603H40]  146.46 157.23 90 bottom
C367  SC1U10V2KX-1DLGP  [C402H22]  76.74 155.57 180 bottom
C368  SC10U6D3V2MX-2-GP  [C402-TO0D2H28]  82.28 154.15 270 bottom
C369  SCD1U16V2KX-3DLGP  [C402H22]  131.1 156.46 90 bottom
C370  SCD1U16V2KX-3DLGP  [C402H22]  69.12 156.46 270 bottom
C371  SC1U10V2KX-1DLGP  [C402H22]  85 155.96 0 bottom
C372  SC1U10V2KX-1DLGP  [C402H22]  82.25 155.07 270 bottom
C373  SC1U10V2KX-1DLGP  [C402H22]  79.18 155.73 90 bottom
C374  SCD1U16V2KX-3DLGP  [C402H22]  69.12 155.57 270 bottom
C375  SC1U10V2KX-1DLGP  [C402H22]  77.63 154.94 0 bottom
C376  SC33P50V2JN-3DLGP  [C402H22]  168.69 153.92 0 bottom
C377  SC22U6D3V3MX-1-DL-GP  [C603H40]  146.46 153.8 90 bottom
C378  SCD1U16V2KX-3DLGP  [C402H22]  139.48 153.54 270 bottom
C379  SC1U10V2KX-1DLGP  [C402H22]  107.6 152.15 270 bottom
C380  SC33P50V2JN-3DLGP  [C402H22]  168.69 152.02 180 bottom
C381  SC1U10V2KX-1DLGP  [C402H22]  107.6 151.26 270 bottom
C382  SC1U10V2KX-1DLGP  [C402H22]  131.22 151 90 bottom
C383  SC4D7U6D3V3KX-DLGP  [C603H36]  173.01 150.88 90 bottom
C384  SCD1U16V2KX-3DLGP  [C402H22]  173.01 149.73 270 bottom
C385  SCD022U16V2KX-3DLGP  [C402H22]  138.97 149.73 180 bottom
C386  SC1U10V2KX-1DLGP  [C402H22]  131.22 149.48 90 bottom
C387  SCD022U16V2KX-3DLGP  [C402H22]  151.04 148.46 270 bottom
C388  SCD1U16V2KX-3DLGP  [C402H22]  154.29 147.9 180 bottom
C389  SCD1U16V2KX-3DLGP  [C402H22]  153.37 147.9 180 bottom
C390  SCD1U16V2KX-3DLGP  [C402H22]  137.83 147.83 180 bottom
C391  SCD1U16V2KX-3DLGP  [C402H22]  136.81 147.83 180 bottom
C392  SC4D7U6D3V3KX-DLGP  [C603H36]  155.63 148.06 180 bottom
C393  SC4D7U6D3V3KX-DLGP  [C603H36]  138.97 147.45 180 bottom
C394  SC33P50V2JN-3DLGP  [C402H22]  169.58 146.81 270 bottom
C395  SC33P50V2JN-3DLGP  [C402H22]  169.58 145.92 270 bottom
C396  SC1U10V2KX-1DLGP  [C402H22]  169.58 142.88 270 bottom
C397  SC6D8P50V2CN-DL-GP  [C402H22]  169.07 141.48 0 bottom
C398  SCD1U16V2KX-3DLGP  [C402H22]  179.87 140.08 180 bottom
C399  SCD1U16V2KX-3DLGP  [C402H22]  178.98 140.08 180 bottom
C400  SCD1U16V2KX-3DLGP  [C402H22]  176.94 139.95 90 bottom
C401  SCD1U16V2KX-3DLGP  [C402H22]  174.79 139.83 90 bottom
C402  SCD1U16V2KX-3DLGP  [C402H22]  173.39 139.45 0 bottom
C403  SC1U10V2KX-1DLGP  [C402H22]  174.79 138.94 90 bottom
C404  SC4D7U6D3V3KX-DLGP  [C603H36]  172.37 138.56 180 bottom
C405  SC4D7U6D3V3KX-DLGP  [C603H36]  174.4 137.85 270 bottom
C406  SCD1U16V2KX-3DLGP  [C402H22]  170.72 137.79 270 bottom
C407  SC10U10V5KX-2DLGP  [C805H50]  176.82 136.91 180 bottom
C408  SC4D7U6D3V3KX-DLGP  [C603H36]  170.34 136.75 90 bottom
C409  SC22U6D3V3MX-1-DL-GP  [C603H40]  154.34 136.65 0 bottom
